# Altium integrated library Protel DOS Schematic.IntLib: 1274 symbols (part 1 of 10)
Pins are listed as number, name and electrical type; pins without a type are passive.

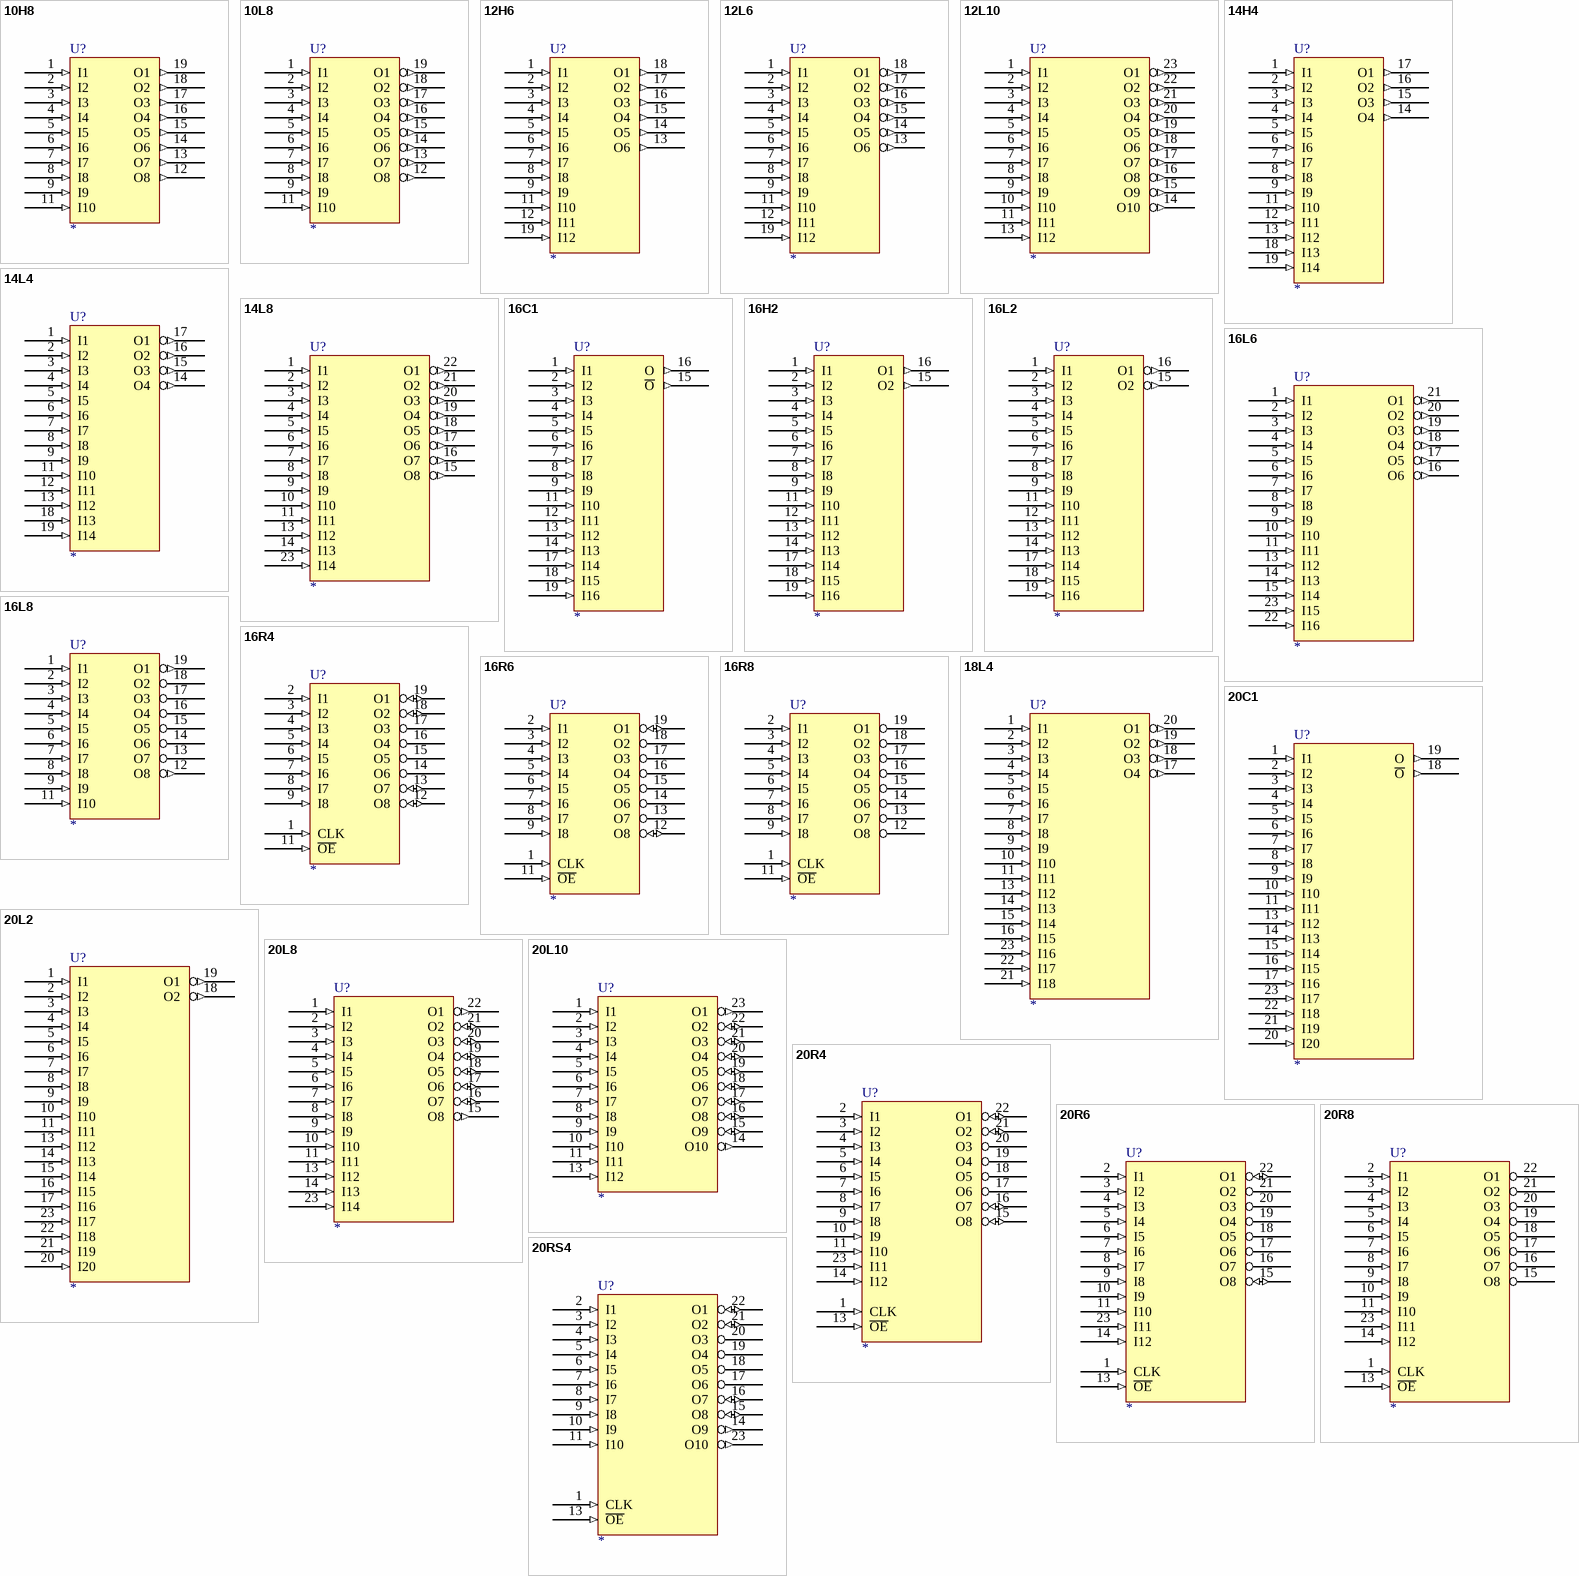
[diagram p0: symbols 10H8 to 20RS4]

## 10H8
designator U?
footprint DIP-20
pins: 1 I1 (in), 2 I2 (in), 3 I3 (in), 4 I4 (in), 5 I5 (in), 6 I6 (in), 7 I7 (in), 8 I8 (in), 9 I9 (in), 10 GND (power) hidden to GND, 11 I10 (in), 12 O8 (out), 13 O7 (out), 14 O6 (out), 15 O5 (out), 16 O4 (out), 17 O3 (out), 18 O2 (out), 19 O1 (out), 20 VCC (power) hidden to VCC
2 alternate drawings of the same symbol

## 10L8
designator U?
footprint DIP-20
pins: 1 I1 (in), 2 I2 (in), 3 I3 (in), 4 I4 (in), 5 I5 (in), 6 I6 (in), 7 I7 (in), 8 I8 (in), 9 I9 (in), 10 GND (power) hidden to GND, 11 I10 (in), 12 O8 (out), 13 O7 (out), 14 O6 (out), 15 O5 (out), 16 O4 (out), 17 O3 (out), 18 O2 (out), 19 O1 (out), 20 VCC (power) hidden to VCC
2 alternate drawings of the same symbol

## 12H6
designator U?
footprint DIP-20
pins: 1 I1 (in), 2 I2 (in), 3 I3 (in), 4 I4 (in), 5 I5 (in), 6 I6 (in), 7 I7 (in), 8 I8 (in), 9 I9 (in), 10 GND (power) hidden to GND, 11 I10 (in), 12 I11 (in), 13 O6 (out), 14 O5 (out), 15 O4 (out), 16 O3 (out), 17 O2 (out), 18 O1 (out), 19 I12 (in), 20 VCC (power) hidden to VCC
2 alternate drawings of the same symbol

## 12L6
designator U?
footprint DIP-20
pins: 1 I1 (in), 2 I2 (in), 3 I3 (in), 4 I4 (in), 5 I5 (in), 6 I6 (in), 7 I7 (in), 8 I8 (in), 9 I9 (in), 10 GND (power) hidden to GND, 11 I10 (in), 12 I11 (in), 13 O6 (out), 14 O5 (out), 15 O4 (out), 16 O3 (out), 17 O2 (out), 18 O1 (out), 19 I12 (in), 20 VCC (power) hidden to VCC
2 alternate drawings of the same symbol

## 12L10
designator U?
footprint DIP-24
pins: 1 I1 (in), 2 I2 (in), 3 I3 (in), 4 I4 (in), 5 I5 (in), 6 I6 (in), 7 I7 (in), 8 I8 (in), 9 I9 (in), 10 I10 (in), 11 I11 (in), 12 GND (power) hidden to GND, 13 I12 (in), 14 O10 (out), 15 O9 (out), 16 O8 (out), 17 O7 (out), 18 O6 (out), 19 O5 (out), 20 O4 (out), 21 O3 (out), 22 O2 (out), 23 O1 (out), 24 VCC (power) hidden to VCC
2 alternate drawings of the same symbol

## 14H4
designator U?
footprint DIP-20
pins: 1 I1 (in), 2 I2 (in), 3 I3 (in), 4 I4 (in), 5 I5 (in), 6 I6 (in), 7 I7 (in), 8 I8 (in), 9 I9 (in), 10 GND (power) hidden to GND, 11 I10 (in), 12 I11 (in), 13 I12 (in), 14 O4 (out), 15 O3 (out), 16 O2 (out), 17 O1 (out), 18 I13 (in), 19 I14 (in), 20 VCC (power) hidden to VCC
2 alternate drawings of the same symbol

## 14L4
designator U?
footprint DIP-20
pins: 1 I1 (in), 2 I2 (in), 3 I3 (in), 4 I4 (in), 5 I5 (in), 6 I6 (in), 7 I7 (in), 8 I8 (in), 9 I9 (in), 10 GND (power) hidden to GND, 11 I10 (in), 12 I11 (in), 13 I12 (in), 14 O4 (out), 15 O3 (out), 16 O2 (out), 17 O1 (out), 18 I13 (in), 19 I14 (in), 20 VCC (power) hidden to VCC
2 alternate drawings of the same symbol

## 14L8
designator U?
footprint DIP-24
pins: 1 I1 (in), 2 I2 (in), 3 I3 (in), 4 I4 (in), 5 I5 (in), 6 I6 (in), 7 I7 (in), 8 I8 (in), 9 I9 (in), 10 I10 (in), 11 I11 (in), 12 GND (power) hidden to GND, 13 I12 (in), 14 I13 (in), 15 O8 (out), 16 O7 (out), 17 O6 (out), 18 O5 (out), 19 O4 (out), 20 O3 (out), 21 O2 (out), 22 O1 (out), 23 I14 (in), 24 VCC (power) hidden to VCC
2 alternate drawings of the same symbol

## 16C1
designator U?
footprint DIP-20
pins: 1 I1 (in), 2 I2 (in), 3 I3 (in), 4 I4 (in), 5 I5 (in), 6 I6 (in), 7 I7 (in), 8 I8 (in), 9 I9 (in), 10 GND (power) hidden to GND, 11 I10 (in), 12 I11 (in), 13 I12 (in), 14 I13 (in), 15 ~{O} (out), 16 O (out), 17 I14 (in), 18 I15 (in), 19 I16 (in), 20 VCC (power) hidden to VCC
2 alternate drawings of the same symbol

## 16H2
designator U?
footprint DIP-20
pins: 1 I1 (in), 2 I2 (in), 3 I3 (in), 4 I4 (in), 5 I5 (in), 6 I6 (in), 7 I7 (in), 8 I8 (in), 9 I9 (in), 10 GND (power) hidden to GND, 11 I10 (in), 12 I11 (in), 13 I12 (in), 14 I13 (in), 15 O2 (out), 16 O1 (out), 17 I14 (in), 18 I15 (in), 19 I16 (in), 20 VCC (power) hidden to VCC
2 alternate drawings of the same symbol

## 16L2
designator U?
footprint DIP-20
pins: 1 I1 (in), 2 I2 (in), 3 I3 (in), 4 I4 (in), 5 I5 (in), 6 I6 (in), 7 I7 (in), 8 I8 (in), 9 I9 (in), 10 GND (power) hidden to GND, 11 I10 (in), 12 I11 (in), 13 I12 (in), 14 I13 (in), 15 O2 (out), 16 O1 (out), 17 I14 (in), 18 I15 (in), 19 I16 (in), 20 VCC (power) hidden to VCC
2 alternate drawings of the same symbol

## 16L6
designator U?
footprint DIP-24
pins: 1 I1 (in), 2 I2 (in), 3 I3 (in), 4 I4 (in), 5 I5 (in), 6 I6 (in), 7 I7 (in), 8 I8 (in), 9 I9 (in), 10 I10 (in), 11 I11 (in), 12 GND (power) hidden to GND, 13 I12 (in), 14 I13 (in), 15 I14 (in), 16 O6 (out), 17 O5 (out), 18 O4 (out), 19 O3 (out), 20 O2 (out), 21 O1 (out), 22 I16 (in), 23 I15 (in), 24 VCC (power) hidden to VCC
2 alternate drawings of the same symbol

## 16L8
designator U?
footprint DIP-20
pins: 1 I1 (in), 2 I2 (in), 3 I3 (in), 4 I4 (in), 5 I5 (in), 6 I6 (in), 7 I7 (in), 8 I8 (in), 9 I9 (in), 10 GND (power) hidden to GND, 11 I10 (in), 12 O8 (out), 13 O7 (hiz), 14 O6 (hiz), 15 O5 (hiz), 16 O4 (hiz), 17 O3 (hiz), 18 O2 (hiz), 19 O1 (out), 20 VCC (power) hidden to VCC
2 alternate drawings of the same symbol

## 16R4
designator U?
footprint DIP-20
pins: 1 CLK (in), 2 I1 (in), 3 I2 (in), 4 I3 (in), 5 I4 (in), 6 I5 (in), 7 I6 (in), 8 I7 (in), 9 I8 (in), 10 GND (power) hidden to GND, 11 ~{OE} (in), 12 O8 (io), 13 O7 (io), 14 O6 (hiz), 15 O5 (hiz), 16 O4 (hiz), 17 O3 (hiz), 18 O2 (io), 19 O1 (io), 20 VCC (power) hidden to VCC
2 alternate drawings of the same symbol

## 16R6
designator U?
footprint DIP-20
pins: 1 CLK (in), 2 I1 (in), 3 I2 (in), 4 I3 (in), 5 I4 (in), 6 I5 (in), 7 I6 (in), 8 I7 (in), 9 I8 (in), 10 GND (power) hidden to GND, 11 ~{OE} (in), 12 O8 (io), 13 O7 (hiz), 14 O6 (hiz), 15 O5 (hiz), 16 O4 (hiz), 17 O3 (hiz), 18 O2 (hiz), 19 O1 (io), 20 VCC (power) hidden to VCC
2 alternate drawings of the same symbol

## 16R8
designator U?
footprint DIP-20
pins: 1 CLK (in), 2 I1 (in), 3 I2 (in), 4 I3 (in), 5 I4 (in), 6 I5 (in), 7 I6 (in), 8 I7 (in), 9 I8 (in), 10 GND (power) hidden to GND, 11 ~{OE} (in), 12 O8 (hiz), 13 O7 (hiz), 14 O6 (hiz), 15 O5 (hiz), 16 O4 (hiz), 17 O3 (hiz), 18 O2 (hiz), 19 O1 (hiz), 20 VCC (power) hidden to VCC
2 alternate drawings of the same symbol

## 18L4
designator U?
footprint DIP-24
pins: 1 I1 (in), 2 I2 (in), 3 I3 (in), 4 I4 (in), 5 I5 (in), 6 I6 (in), 7 I7 (in), 8 I8 (in), 9 I9 (in), 10 I10 (in), 11 I11 (in), 12 GND (power) hidden to GND, 13 I12 (in), 14 I13 (in), 15 I14 (in), 16 I15 (in), 17 O4 (out), 18 O3 (out), 19 O2 (out), 20 O1 (out), 21 I18 (in), 22 I17 (in), 23 I16 (in), 24 VCC (power) hidden to VCC
2 alternate drawings of the same symbol

## 20C1
designator U?
footprint DIP-24
pins: 1 I1 (in), 2 I2 (in), 3 I3 (in), 4 I4 (in), 5 I5 (in), 6 I6 (in), 7 I7 (in), 8 I8 (in), 9 I9 (in), 10 I10 (in), 11 I11 (in), 12 GND (power) hidden to GND, 13 I12 (in), 14 I13 (in), 15 I14 (in), 16 I15 (in), 17 I16 (in), 18 ~{O} (out), 19 O (out), 20 I20 (in), 21 I19 (in), 22 I18 (in), 23 I17 (in), 24 VCC (power) hidden to VCC
2 alternate drawings of the same symbol

## 20L2
designator U?
footprint DIP-24
pins: 1 I1 (in), 2 I2 (in), 3 I3 (in), 4 I4 (in), 5 I5 (in), 6 I6 (in), 7 I7 (in), 8 I8 (in), 9 I9 (in), 10 I10 (in), 11 I11 (in), 12 GND (power) hidden to GND, 13 I12 (in), 14 I13 (in), 15 I14 (in), 16 I15 (in), 17 I16 (in), 18 O2 (out), 19 O1 (out), 20 I20 (in), 21 I19 (in), 22 I18 (in), 23 I17 (in), 24 VCC (power) hidden to VCC
2 alternate drawings of the same symbol

## 20L8
designator U?
footprint DIP-24
pins: 1 I1 (in), 2 I2 (in), 3 I3 (in), 4 I4 (in), 5 I5 (in), 6 I6 (in), 7 I7 (in), 8 I8 (in), 9 I9 (in), 10 I10 (in), 11 I11 (in), 12 GND (power) hidden to GND, 13 I12 (in), 14 I13 (in), 15 O8 (out), 16 O7 (io), 17 O6 (io), 18 O5 (io), 19 O4 (io), 20 O3 (io), 21 O2 (io), 22 O1 (out), 23 I14 (in), 24 VCC (power) hidden to VCC
2 alternate drawings of the same symbol

## 20L10
designator U?
footprint DIP-24
pins: 1 I1 (in), 2 I2 (in), 3 I3 (in), 4 I4 (in), 5 I5 (in), 6 I6 (in), 7 I7 (in), 8 I8 (in), 9 I9 (in), 10 I10 (in), 11 I11 (in), 12 GND (power) hidden to GND, 13 I12 (in), 14 O10 (out), 15 O9 (io), 16 O8 (io), 17 O7 (io), 18 O6 (io), 19 O5 (io), 20 O4 (io), 21 O3 (io), 22 O2 (io), 23 O1 (out), 24 VCC (power) hidden to VCC
2 alternate drawings of the same symbol

## 20R4
designator U?
footprint DIP-24
pins: 1 CLK (in), 2 I1 (in), 3 I2 (in), 4 I3 (in), 5 I4 (in), 6 I5 (in), 7 I6 (in), 8 I7 (in), 9 I8 (in), 10 I9 (in), 11 I10 (in), 12 GND (power) hidden to GND, 13 ~{OE} (in), 14 I12 (in), 15 O8 (io), 16 O7 (io), 17 O6 (hiz), 18 O5 (hiz), 19 O4 (hiz), 20 O3 (hiz), 21 O2 (io), 22 O1 (io), 23 I11 (in), 24 VCC (power) hidden to VCC
2 alternate drawings of the same symbol

## 20R6
designator U?
footprint DIP-24
pins: 1 CLK (in), 2 I1 (in), 3 I2 (in), 4 I3 (in), 5 I4 (in), 6 I5 (in), 7 I6 (in), 8 I7 (in), 9 I8 (in), 10 I9 (in), 11 I10 (in), 12 GND (power) hidden to GND, 13 ~{OE} (in), 14 I12 (in), 15 O8 (io), 16 O7 (hiz), 17 O6 (hiz), 18 O5 (hiz), 19 O4 (hiz), 20 O3 (hiz), 21 O2 (hiz), 22 O1 (io), 23 I11 (in), 24 VCC (power) hidden to VCC
2 alternate drawings of the same symbol

## 20R8
designator U?
footprint DIP-24
pins: 1 CLK (in), 2 I1 (in), 3 I2 (in), 4 I3 (in), 5 I4 (in), 6 I5 (in), 7 I6 (in), 8 I7 (in), 9 I8 (in), 10 I9 (in), 11 I10 (in), 12 GND (power) hidden to GND, 13 ~{OE} (in), 14 I12 (in), 15 O8 (hiz), 16 O7 (hiz), 17 O6 (hiz), 18 O5 (hiz), 19 O4 (hiz), 20 O3 (hiz), 21 O2 (hiz), 22 O1 (hiz), 23 I11 (in), 24 VCC (power) hidden to VCC
2 alternate drawings of the same symbol

## 20RS4
designator U?
footprint DIP-24
pins: 1 CLK (in), 2 I1 (in), 3 I2 (in), 4 I3 (in), 5 I4 (in), 6 I5 (in), 7 I6 (in), 8 I7 (in), 9 I8 (in), 10 I9 (in), 11 I10 (in), 12 GND (power) hidden to GND, 13 ~{OE} (in), 14 O9 (out), 15 O8 (io), 16 O7 (io), 17 O6 (hiz), 18 O5 (hiz), 19 O4 (hiz), 20 O3 (hiz), 21 O2 (io), 22 O1 (io), 23 O10 (out), 24 VCC (power) hidden to VCC
2 alternate drawings of the same symbol

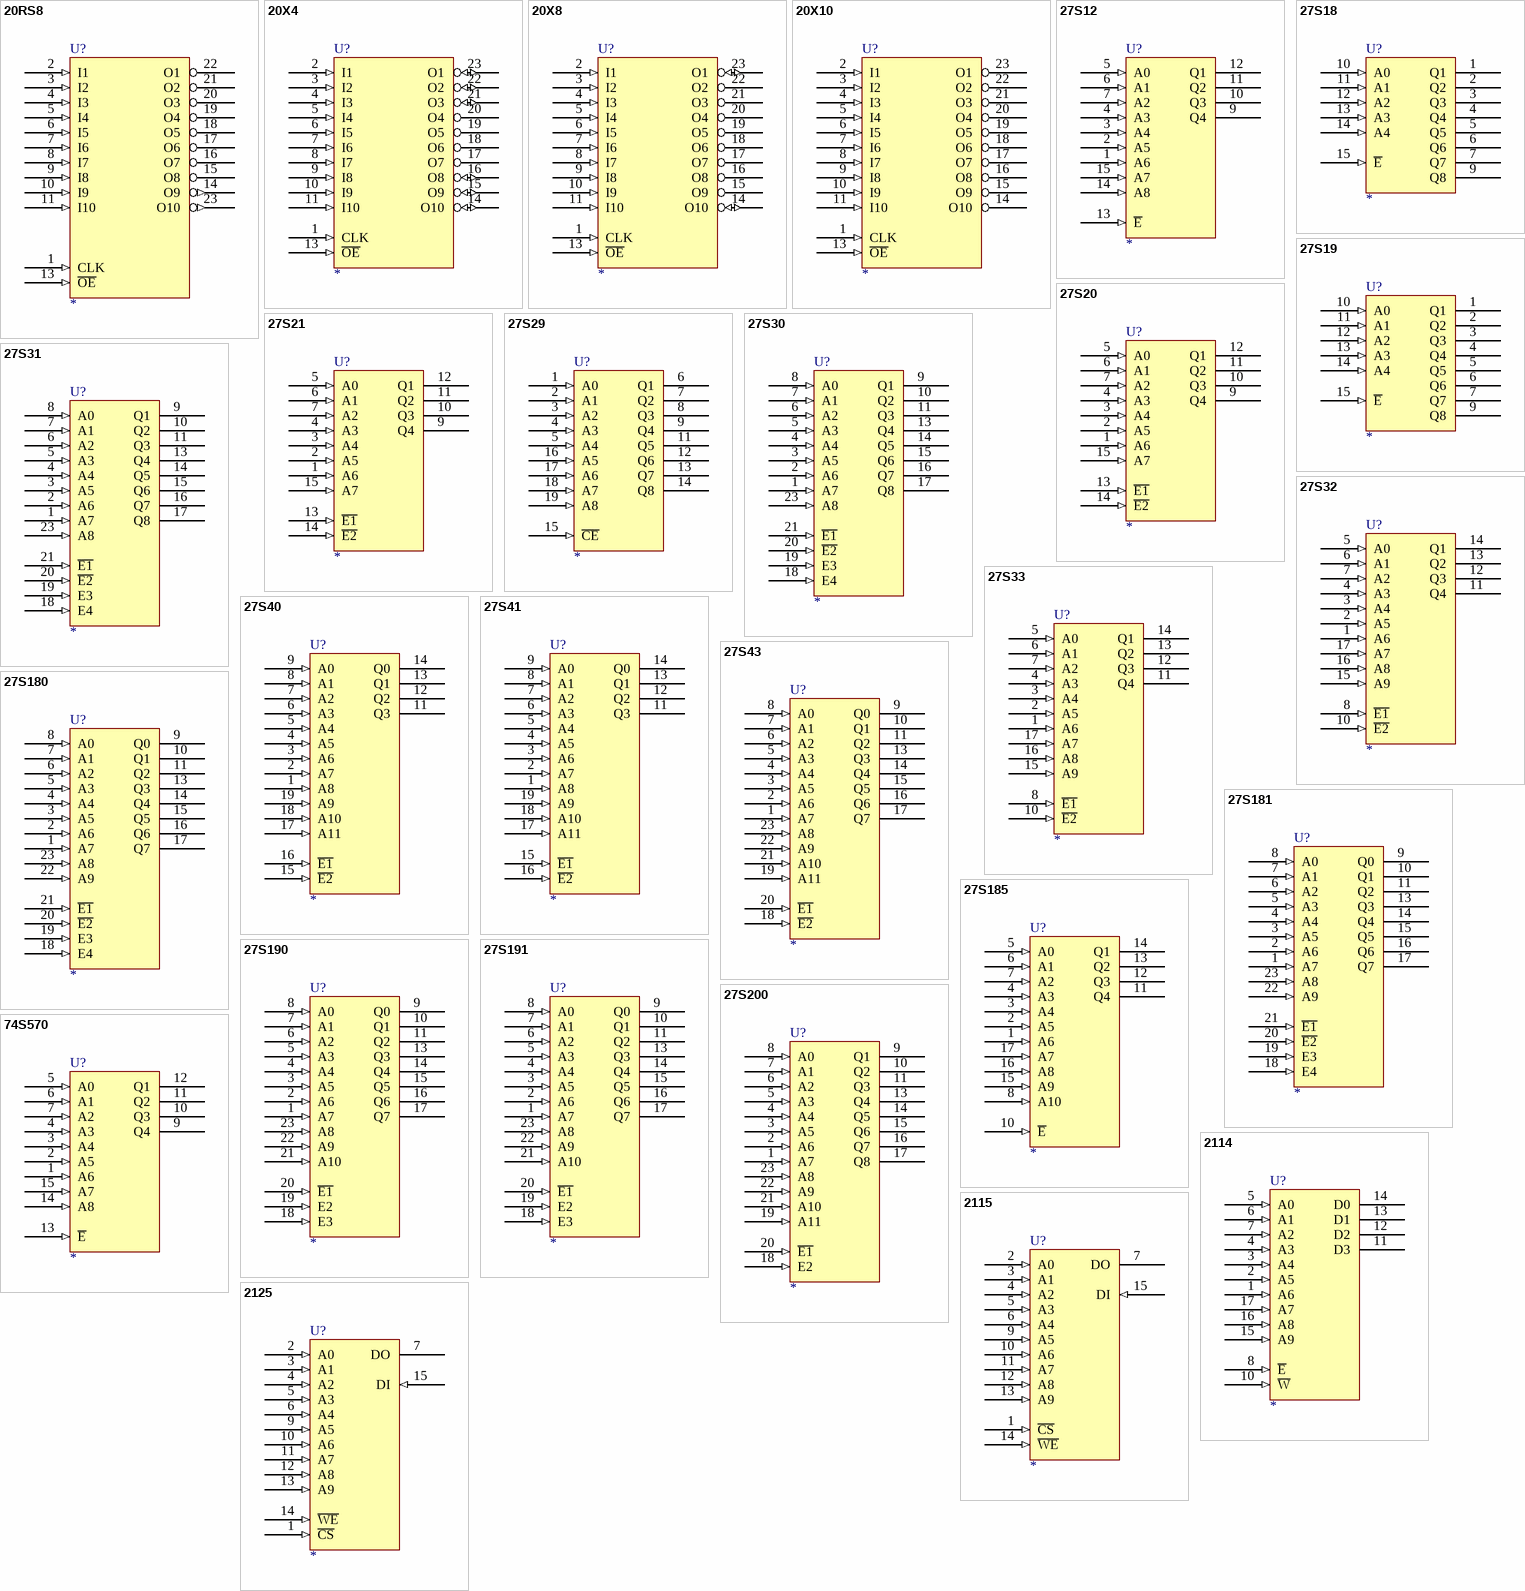
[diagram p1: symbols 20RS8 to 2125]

## 20RS8
designator U?
footprint DIP-24
pins: 1 CLK (in), 2 I1 (in), 3 I2 (in), 4 I3 (in), 5 I4 (in), 6 I5 (in), 7 I6 (in), 8 I7 (in), 9 I8 (in), 10 I9 (in), 11 I10 (in), 12 GND (power) hidden to GND, 13 ~{OE} (in), 14 O9 (out), 15 O8 (hiz), 16 O7 (hiz), 17 O6 (hiz), 18 O5 (hiz), 19 O4 (hiz), 20 O3 (hiz), 21 O2 (hiz), 22 O1 (hiz), 23 O10 (out), 24 VCC (power) hidden to VCC
2 alternate drawings of the same symbol

## 20X4
designator U?
footprint DIP-24
pins: 1 CLK (in), 2 I1 (in), 3 I2 (in), 4 I3 (in), 5 I4 (in), 6 I5 (in), 7 I6 (in), 8 I7 (in), 9 I8 (in), 10 I9 (in), 11 I10 (in), 12 GND (power) hidden to GND, 13 ~{OE} (in), 14 O10 (io), 15 O9 (io), 16 O8 (io), 17 O7 (hiz), 18 O6 (hiz), 19 O5 (hiz), 20 O4 (hiz), 21 O3 (io), 22 O2 (io), 23 O1 (io), 24 VCC (power) hidden to VCC
2 alternate drawings of the same symbol

## 20X8
designator U?
footprint DIP-24
pins: 1 CLK (in), 2 I1 (in), 3 I2 (in), 4 I3 (in), 5 I4 (in), 6 I5 (in), 7 I6 (in), 8 I7 (in), 9 I8 (in), 10 I9 (in), 11 I10 (in), 12 GND (power) hidden to GND, 13 ~{OE} (in), 14 O10 (io), 15 O9 (hiz), 16 O8 (hiz), 17 O7 (hiz), 18 O6 (hiz), 19 O5 (hiz), 20 O4 (hiz), 21 O3 (hiz), 22 O2 (hiz), 23 O1 (io), 24 VCC (power) hidden to VCC
2 alternate drawings of the same symbol

## 20X10
designator U?
footprint DIP-24
pins: 1 CLK (in), 2 I1 (in), 3 I2 (in), 4 I3 (in), 5 I4 (in), 6 I5 (in), 7 I6 (in), 8 I7 (in), 9 I8 (in), 10 I9 (in), 11 I10 (in), 12 GND (power) hidden to GND, 13 ~{OE} (in), 14 O10 (hiz), 15 O9 (hiz), 16 O8 (hiz), 17 O7 (hiz), 18 O6 (hiz), 19 O5 (hiz), 20 O4 (hiz), 21 O3 (hiz), 22 O2 (hiz), 23 O1 (hiz), 24 VCC (power) hidden to VCC
2 alternate drawings of the same symbol

## 27S12
designator U?
footprint DIP-16
pins: 1 A6 (in), 2 A5 (in), 3 A4 (in), 4 A3 (in), 5 A0 (in), 6 A1 (in), 7 A2 (in), 8 GND (power) hidden to GND, 9 Q4 (hiz), 10 Q3 (hiz), 11 Q2 (hiz), 12 Q1 (hiz), 13 ~{E} (in), 14 A8 (in), 15 A7 (in), 16 VCC (power) hidden to VCC
2 alternate drawings of the same symbol

## 27S18
designator U?
footprint DIP-16
pins: 1 Q1 (oc), 2 Q2 (oc), 3 Q3 (oc), 4 Q4 (oc), 5 Q5 (oc), 6 Q6 (oc), 7 Q7 (oc), 8 GND (power) hidden to GND, 9 Q8 (oc), 10 A0 (in), 11 A1 (in), 12 A2 (in), 13 A3 (in), 14 A4 (in), 15 ~{E} (in), 16 VCC (power) hidden to VCC
2 alternate drawings of the same symbol

## 27S19
designator U?
footprint DIP-16
pins: 1 Q1 (hiz), 2 Q2 (hiz), 3 Q3 (hiz), 4 Q4 (hiz), 5 Q5 (hiz), 6 Q6 (hiz), 7 Q7 (hiz), 8 GND (power) hidden to GND, 9 Q8 (hiz), 10 A0 (in), 11 A1 (in), 12 A2 (in), 13 A3 (in), 14 A4 (in), 15 ~{E} (in), 16 VCC (power) hidden to VCC
2 alternate drawings of the same symbol

## 27S20
designator U?
footprint DIP-16
pins: 1 A6 (in), 2 A5 (in), 3 A4 (in), 4 A3 (in), 5 A0 (in), 6 A1 (in), 7 A2 (in), 8 GND (power) hidden to GND, 9 Q4 (oc), 10 Q3 (oc), 11 Q2 (oc), 12 Q1 (oc), 13 ~{E1} (in), 14 ~{E2} (in), 15 A7 (in), 16 VCC (power) hidden to VCC
2 alternate drawings of the same symbol

## 27S21
designator U?
footprint DIP-16
pins: 1 A6 (in), 2 A5 (in), 3 A4 (in), 4 A3 (in), 5 A0 (in), 6 A1 (in), 7 A2 (in), 8 GND (power) hidden to GND, 9 Q4 (hiz), 10 Q3 (hiz), 11 Q2 (hiz), 12 Q1 (hiz), 13 ~{E1} (in), 14 ~{E2} (in), 15 A7 (in), 16 VCC (power) hidden to VCC
2 alternate drawings of the same symbol

## 27S29
designator U?
footprint DIP-20
pins: 1 A0 (in), 2 A1 (in), 3 A2 (in), 4 A3 (in), 5 A4 (in), 6 Q1 (hiz), 7 Q2 (hiz), 8 Q3 (hiz), 9 Q4 (hiz), 10 GND (power) hidden to GND, 11 Q5 (hiz), 12 Q6 (hiz), 13 Q7 (hiz), 14 Q8 (hiz), 15 ~{CE} (in), 16 A5 (in), 17 A6 (in), 18 A7 (in), 19 A8 (in), 20 VCC (power) hidden to VCC
2 alternate drawings of the same symbol

## 27S30
designator U?
footprint DIP-24
pins: 1 A7 (in), 2 A6 (in), 3 A5 (in), 4 A4 (in), 5 A3 (in), 6 A2 (in), 7 A1 (in), 8 A0 (in), 9 Q1 (oc), 10 Q2 (oc), 11 Q3 (oc), 12 GND (power) hidden to GND, 13 Q4 (oc), 14 Q5 (oc), 15 Q6 (oc), 16 Q7 (oc), 17 Q8 (oc), 18 E4 (in), 19 E3 (in), 20 ~{E2} (in), 21 ~{E1} (in), 23 A8 (in), 24 VCC (power) hidden to VCC
2 alternate drawings of the same symbol

## 27S31
designator U?
footprint DIP-24
pins: 1 A7 (in), 2 A6 (in), 3 A5 (in), 4 A4 (in), 5 A3 (in), 6 A2 (in), 7 A1 (in), 8 A0 (in), 9 Q1 (hiz), 10 Q2 (hiz), 11 Q3 (hiz), 12 GND (power) hidden to GND, 13 Q4 (hiz), 14 Q5 (hiz), 15 Q6 (hiz), 16 Q7 (hiz), 17 Q8 (hiz), 18 E4 (in), 19 E3 (in), 20 ~{E2} (in), 21 ~{E1} (in), 23 A8 (in), 24 VCC (power) hidden to VCC
2 alternate drawings of the same symbol

## 27S32
designator U?
footprint DIP-18
pins: 1 A6 (in), 2 A5 (in), 3 A4 (in), 4 A3 (in), 5 A0 (in), 6 A1 (in), 7 A2 (in), 8 ~{E1} (in), 9 GND (power) hidden to GND, 10 ~{E2} (in), 11 Q4 (oc), 12 Q3 (oc), 13 Q2 (oc), 14 Q1 (oc), 15 A9 (in), 16 A8 (in), 17 A7 (in), 18 VCC (power) hidden to VCC
2 alternate drawings of the same symbol

## 27S33
designator U?
footprint DIP-18
pins: 1 A6 (in), 2 A5 (in), 3 A4 (in), 4 A3 (in), 5 A0 (in), 6 A1 (in), 7 A2 (in), 8 ~{E1} (in), 9 GND (power) hidden to GND, 10 ~{E2} (in), 11 Q4 (hiz), 12 Q3 (hiz), 13 Q2 (hiz), 14 Q1 (hiz), 15 A9 (in), 16 A8 (in), 17 A7 (in), 18 VCC (power) hidden to VCC
2 alternate drawings of the same symbol

## 27S40
designator U?
footprint DIP-20
pins: 1 A8 (in), 2 A7 (in), 3 A6 (in), 4 A5 (in), 5 A4 (in), 6 A3 (in), 7 A2 (in), 8 A1 (in), 9 A0 (in), 10 GND (power) hidden to GND, 11 Q3 (oc), 12 Q2 (oc), 13 Q1 (oc), 14 Q0 (oc), 15 ~{E2} (in), 16 ~{E1} (in), 17 A11 (in), 18 A10 (in), 19 A9 (in), 20 VCC (power) hidden to VCC
2 alternate drawings of the same symbol

## 27S41
designator U?
footprint DIP-20
pins: 1 A8 (in), 2 A7 (in), 3 A6 (in), 4 A5 (in), 5 A4 (in), 6 A3 (in), 7 A2 (in), 8 A1 (in), 9 A0 (in), 10 GND (power) hidden to GND, 11 Q3 (hiz), 12 Q2 (hiz), 13 Q1 (hiz), 14 Q0 (hiz), 15 ~{E1} (in), 16 ~{E2} (in), 17 A11 (in), 18 A10 (in), 19 A9 (in), 20 VCC (power) hidden to VCC
2 alternate drawings of the same symbol

## 27S43
designator U?
footprint DIP-24
pins: 1 A7 (in), 2 A6 (in), 3 A5 (in), 4 A4 (in), 5 A3 (in), 6 A2 (in), 7 A1 (in), 8 A0 (in), 9 Q0 (hiz), 10 Q1 (hiz), 11 Q2 (hiz), 12 GND (power) hidden to GND, 13 Q3 (hiz), 14 Q4 (hiz), 15 Q5 (hiz), 16 Q6 (hiz), 17 Q7 (hiz), 18 ~{E2} (in), 19 A11 (in), 20 ~{E1} (in), 21 A10 (in), 22 A9 (in), 23 A8 (in), 24 VCC (power) hidden to VCC
2 alternate drawings of the same symbol

## 27S180
designator U?
footprint DIP-24
pins: 1 A7 (in), 2 A6 (in), 3 A5 (in), 4 A4 (in), 5 A3 (in), 6 A2 (in), 7 A1 (in), 8 A0 (in), 9 Q0 (oc), 10 Q1 (oc), 11 Q2 (oc), 12 GND (power) hidden to GND, 13 Q3 (oc), 14 Q4 (oc), 15 Q5 (oc), 16 Q6 (oc), 17 Q7 (oc), 18 E4 (in), 19 E3 (in), 20 ~{E2} (in), 21 ~{E1} (in), 22 A9 (in), 23 A8 (in), 24 VCC (power) hidden to VCC
2 alternate drawings of the same symbol

## 27S181
designator U?
footprint DIP-24
pins: 1 A7 (in), 2 A6 (in), 3 A5 (in), 4 A4 (in), 5 A3 (in), 6 A2 (in), 7 A1 (in), 8 A0 (in), 9 Q0 (hiz), 10 Q1 (hiz), 11 Q2 (hiz), 12 GND (power) hidden to GND, 13 Q3 (hiz), 14 Q4 (hiz), 15 Q5 (hiz), 16 Q6 (hiz), 17 Q7 (hiz), 18 E4 (in), 19 E3 (in), 20 ~{E2} (in), 21 ~{E1} (in), 22 A9 (in), 23 A8 (in), 24 VCC (power) hidden to VCC
2 alternate drawings of the same symbol

## 27S185
designator U?
footprint DIP-18
pins: 1 A6 (in), 2 A5 (in), 3 A4 (in), 4 A3 (in), 5 A0 (in), 6 A1 (in), 7 A2 (in), 8 A10 (in), 9 GND (power) hidden to GND, 10 ~{E} (in), 11 Q4 (hiz), 12 Q3 (hiz), 13 Q2 (hiz), 14 Q1 (hiz), 15 A9 (in), 16 A8 (in), 17 A7 (in), 18 VCC (power) hidden to VCC
2 alternate drawings of the same symbol

## 27S190
designator U?
footprint DIP-24
pins: 1 A7 (in), 2 A6 (in), 3 A5 (in), 4 A4 (in), 5 A3 (in), 6 A2 (in), 7 A1 (in), 8 A0 (in), 9 Q0 (oc), 10 Q1 (oc), 11 Q2 (oc), 12 GND (power) hidden to GND, 13 Q3 (oc), 14 Q4 (oc), 15 Q5 (oc), 16 Q6 (oc), 17 Q7 (oc), 18 E3 (in), 19 E2 (in), 20 ~{E1} (in), 21 A10 (in), 22 A9 (in), 23 A8 (in), 24 VCC (power) hidden to VCC
2 alternate drawings of the same symbol

## 27S191
designator U?
footprint DIP-24
pins: 1 A7 (in), 2 A6 (in), 3 A5 (in), 4 A4 (in), 5 A3 (in), 6 A2 (in), 7 A1 (in), 8 A0 (in), 9 Q0 (hiz), 10 Q1 (hiz), 11 Q2 (hiz), 12 GND (power) hidden to GND, 13 Q3 (hiz), 14 Q4 (hiz), 15 Q5 (hiz), 16 Q6 (hiz), 17 Q7 (hiz), 18 E3 (in), 19 E2 (in), 20 ~{E1} (in), 21 A10 (in), 22 A9 (in), 23 A8 (in), 24 VCC (power) hidden to VCC
2 alternate drawings of the same symbol

## 27S200
designator U?
footprint DIP-24
pins: 1 A7 (in), 2 A6 (in), 3 A5 (in), 4 A4 (in), 5 A3 (in), 6 A2 (in), 7 A1 (in), 8 A0 (in), 9 Q1 (hiz), 10 Q2 (hiz), 11 Q3 (hiz), 12 GND (power) hidden to GND, 13 Q4 (hiz), 14 Q5 (hiz), 15 Q6 (hiz), 16 Q7 (hiz), 17 Q8 (hiz), 18 E2 (in), 19 A11 (in), 20 ~{E1} (in), 21 A10 (in), 22 A9 (in), 23 A8 (in), 24 VCC (power) hidden to VCC
2 alternate drawings of the same symbol

## 74S570
designator U?
footprint DIP-16
pins: 1 A6 (in), 2 A5 (in), 3 A4 (in), 4 A3 (in), 5 A0 (in), 6 A1 (in), 7 A2 (in), 8 GND (power) hidden to GND, 9 Q4 (oc), 10 Q3 (oc), 11 Q2 (oc), 12 Q1 (oc), 13 ~{E} (in), 14 A8 (in), 15 A7 (in), 16 VCC (power) hidden to VCC
2 alternate drawings of the same symbol

## 2114
designator U?
footprint DIP-18
pins: 1 A6 (in), 2 A5 (in), 3 A4 (in), 4 A3 (in), 5 A0 (in), 6 A1 (in), 7 A2 (in), 8 ~{E} (in), 9 GND (power) hidden to GND, 10 ~{W} (in), 11 D3 (hiz), 12 D2 (hiz), 13 D1 (hiz), 14 D0 (hiz), 15 A9 (in), 16 A8 (in), 17 A7 (in), 18 VCC (power) hidden to VCC
2 alternate drawings of the same symbol

## 2115
designator U?
footprint DIP-16
pins: 1 ~{CS} (in), 2 A0 (in), 3 A1 (in), 4 A2 (in), 5 A3 (in), 6 A4 (in), 7 DO (oc), 8 GND (power) hidden to GND, 9 A5 (in), 10 A6 (in), 11 A7 (in), 12 A8 (in), 13 A9 (in), 14 ~{WE} (in), 15 DI (in), 16 VCC (power) hidden to VCC
2 alternate drawings of the same symbol

## 2125
designator U?
footprint DIP-16
pins: 1 ~{CS} (in), 2 A0 (in), 3 A1 (in), 4 A2 (in), 5 A3 (in), 6 A4 (in), 7 DO (hiz), 8 GND (power) hidden to GND, 9 A5 (in), 10 A6 (in), 11 A7 (in), 12 A8 (in), 13 A9 (in), 14 ~{WE} (in), 15 DI (in), 16 VCC (power) hidden to VCC
2 alternate drawings of the same symbol

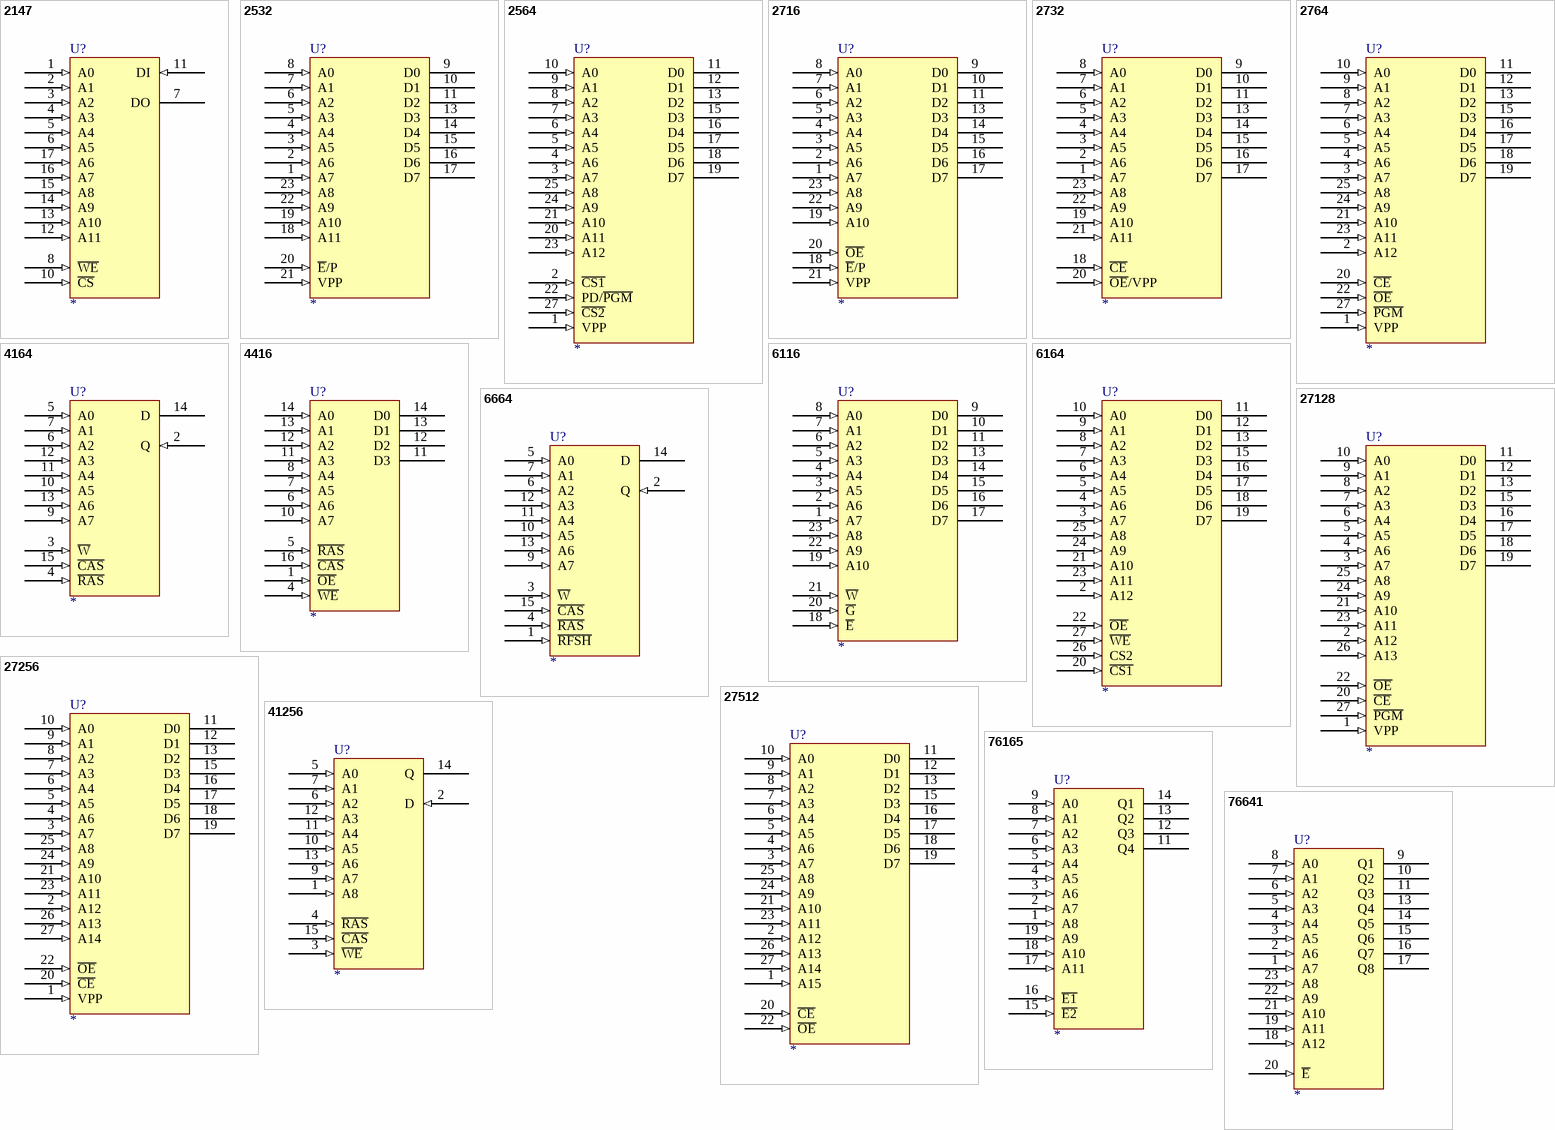
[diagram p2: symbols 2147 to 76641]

## 2147
designator U?
footprint DIP-18
pins: 1 A0 (in), 2 A1 (in), 3 A2 (in), 4 A3 (in), 5 A4 (in), 6 A5 (in), 7 DO (hiz), 8 ~{WE} (in), 9 GND (power) hidden to GND, 10 ~{CS} (in), 11 DI (in), 12 A11 (in), 13 A10 (in), 14 A9 (in), 15 A8 (in), 16 A7 (in), 17 A6 (in), 18 VCC (power) hidden to VCC
2 alternate drawings of the same symbol

## 2532
designator U?
footprint DIP-24
pins: 1 A7 (in), 2 A6 (in), 3 A5 (in), 4 A4 (in), 5 A3 (in), 6 A2 (in), 7 A1 (in), 8 A0 (in), 9 D0 (hiz), 10 D1 (hiz), 11 D2 (hiz), 12 GND (power) hidden to GND, 13 D3 (hiz), 14 D4 (hiz), 15 D5 (hiz), 16 D6 (hiz), 17 D7 (hiz), 18 A11 (in), 19 A10 (in), 20 ~{E}/P (in), 21 VPP (in), 22 A9 (in), 23 A8 (in), 24 VCC (power) hidden to VCC
2 alternate drawings of the same symbol

## 2564
designator U?
footprint DIP-24
pins: 1 VPP (in), 2 ~{CS1} (in), 3 A7 (in), 4 A6 (in), 5 A5 (in), 6 A4 (in), 7 A3 (in), 8 A2 (in), 9 A1 (in), 10 A0 (in), 11 D0 (hiz), 12 D1 (hiz), 13 D2 (hiz), 14 GND (power) hidden to GND, 15 D3 (hiz), 16 D4 (hiz), 17 D5 (hiz), 18 D6 (hiz), 19 D7 (hiz), 20 A11 (in), 21 A10 (in), 22 PD/~{PGM} (in), 23 A12 (in), 24 A9 (in), 25 A8 (in), 27 ~{CS2} (in), 28 VCC (power) hidden to VCC
2 alternate drawings of the same symbol

## 2716
designator U?
footprint DIP-24
pins: 1 A7 (in), 2 A6 (in), 3 A5 (in), 4 A4 (in), 5 A3 (in), 6 A2 (in), 7 A1 (in), 8 A0 (in), 9 D0 (hiz), 10 D1 (hiz), 11 D2 (hiz), 12 GND (power) hidden to GND, 13 D3 (hiz), 14 D4 (hiz), 15 D5 (hiz), 16 D6 (hiz), 17 D7 (hiz), 18 ~{E}/P (in), 19 A10 (in), 20 ~{OE} (in), 21 VPP (in), 22 A9 (in), 23 A8 (in), 24 VCC (power) hidden to VCC
2 alternate drawings of the same symbol

## 2732
designator U?
footprint DIP-24
pins: 1 A7 (in), 2 A6 (in), 3 A5 (in), 4 A4 (in), 5 A3 (in), 6 A2 (in), 7 A1 (in), 8 A0 (in), 9 D0 (hiz), 10 D1 (hiz), 11 D2 (hiz), 12 GND (power) hidden to GND, 13 D3 (hiz), 14 D4 (hiz), 15 D5 (hiz), 16 D6 (hiz), 17 D7 (hiz), 18 ~{CE} (in), 19 A10 (in), 20 ~{OE}/VPP (in), 21 A11 (in), 22 A9 (in), 23 A8 (in), 24 VCC (power) hidden to VCC
2 alternate drawings of the same symbol

## 2764
designator U?
footprint DIP-28
pins: 1 VPP (in), 2 A12 (in), 3 A7 (in), 4 A6 (in), 5 A5 (in), 6 A4 (in), 7 A3 (in), 8 A2 (in), 9 A1 (in), 10 A0 (in), 11 D0 (hiz), 12 D1 (hiz), 13 D2 (hiz), 14 GND (power) hidden to GND, 15 D3 (hiz), 16 D4 (hiz), 17 D5 (hiz), 18 D6 (hiz), 19 D7 (hiz), 20 ~{CE} (in), 21 A10 (in), 22 ~{OE} (in), 23 A11 (in), 24 A9 (in), 25 A8 (in), 27 ~{PGM} (in), 28 VCC (power) hidden to VCC
2 alternate drawings of the same symbol

## 4164
designator U?
footprint DIP-16
pins: 2 Q (in), 3 ~{W} (in), 4 ~{RAS} (in), 5 A0 (in), 6 A2 (in), 7 A1 (in), 8 VCC (power) hidden to VCC, 9 A7 (in), 10 A5 (in), 11 A4 (in), 12 A3 (in), 13 A6 (in), 14 D (hiz), 15 ~{CAS} (in), 16 GND (power) hidden to GND
2 alternate drawings of the same symbol

## 4416
designator U?
footprint DIP-18
pins: 1 ~{OE} (in), 4 ~{WE} (in), 5 ~{RAS} (in), 6 A6 (in), 7 A5 (in), 8 A4 (in), 9 VCC (power) hidden to VCC, 10 A7 (in), 11 A3 (in), 11 D3 (hiz), 12 A2 (in), 12 D2 (hiz), 13 A1 (in), 13 D1 (hiz), 14 A0 (in), 14 D0 (hiz), 16 ~{CAS} (in), 18 GND (power) hidden to GND
2 alternate drawings of the same symbol

## 6116
designator U?
footprint DIP-24
pins: 1 A7 (in), 2 A6 (in), 3 A5 (in), 4 A4 (in), 5 A3 (in), 6 A2 (in), 7 A1 (in), 8 A0 (in), 9 D0 (hiz), 10 D1 (hiz), 11 D2 (hiz), 12 GND (power) hidden to GND, 13 D3 (hiz), 14 D4 (hiz), 15 D5 (hiz), 16 D6 (hiz), 17 D7 (hiz), 18 ~{E} (in), 19 A10 (in), 20 ~{G} (in), 21 ~{W} (in), 22 A9 (in), 23 A8 (in), 24 VCC (power) hidden to VCC
2 alternate drawings of the same symbol

## 6164
designator U?
footprint DIP-28
pins: 2 A12 (in), 3 A7 (in), 4 A6 (in), 5 A5 (in), 6 A4 (in), 7 A3 (in), 8 A2 (in), 9 A1 (in), 10 A0 (in), 11 D0 (hiz), 12 D1 (hiz), 13 D2 (hiz), 14 GND (power) hidden to GND, 15 D3 (hiz), 16 D4 (hiz), 17 D5 (hiz), 18 D6 (hiz), 19 D7 (hiz), 20 ~{CS1} (in), 21 A10 (in), 22 ~{OE} (in), 23 A11 (in), 24 A9 (in), 25 A8 (in), 26 CS2 (in), 27 ~{WE} (in), 28 VCC (power) hidden to VCC
2 alternate drawings of the same symbol

## 6664
designator U?
footprint DIP-16
pins: 1 ~{RFSH} (in), 2 Q (in), 3 ~{W} (in), 4 ~{RAS} (in), 5 A0 (in), 6 A2 (in), 7 A1 (in), 8 VCC (power) hidden to VCC, 9 A7 (in), 10 A5 (in), 11 A4 (in), 12 A3 (in), 13 A6 (in), 14 D (hiz), 15 ~{CAS} (in), 16 GND (power) hidden to GND
2 alternate drawings of the same symbol

## 27128
designator U?
footprint DIP-28
pins: 1 VPP (in), 2 A12 (in), 3 A7 (in), 4 A6 (in), 5 A5 (in), 6 A4 (in), 7 A3 (in), 8 A2 (in), 9 A1 (in), 10 A0 (in), 11 D0 (hiz), 12 D1 (hiz), 13 D2 (hiz), 14 GND (power) hidden to GND, 15 D3 (hiz), 16 D4 (hiz), 17 D5 (hiz), 18 D6 (hiz), 19 D7 (hiz), 20 ~{CE} (in), 21 A10 (in), 22 ~{OE} (in), 23 A11 (in), 24 A9 (in), 25 A8 (in), 26 A13 (in), 27 ~{PGM} (in), 28 VCC (power) hidden to VCC
2 alternate drawings of the same symbol

## 27256
designator U?
footprint DIP-28
footprint DIP28-O
pins: 1 VPP (in), 2 A12 (in), 3 A7 (in), 4 A6 (in), 5 A5 (in), 6 A4 (in), 7 A3 (in), 8 A2 (in), 9 A1 (in), 10 A0 (in), 11 D0 (hiz), 12 D1 (hiz), 13 D2 (hiz), 14 GND (power) hidden to GND, 15 D3 (hiz), 16 D4 (hiz), 17 D5 (hiz), 18 D6 (hiz), 19 D7 (hiz), 20 ~{CE} (in), 21 A10 (in), 22 ~{OE} (in), 23 A11 (in), 24 A9 (in), 25 A8 (in), 26 A13 (in), 27 A14 (in), 28 VCC (power) hidden to VCC
2 alternate drawings of the same symbol

## 27512
designator U?
footprint DIP-28
pins: 1 A15 (in), 2 A12 (in), 3 A7 (in), 4 A6 (in), 5 A5 (in), 6 A4 (in), 7 A3 (in), 8 A2 (in), 9 A1 (in), 10 A0 (in), 11 D0 (hiz), 12 D1 (hiz), 13 D2 (hiz), 14 GND (power) hidden to GND, 15 D3 (hiz), 16 D4 (hiz), 17 D5 (hiz), 18 D6 (hiz), 19 D7 (hiz), 20 ~{CE} (in), 21 A10 (in), 22 ~{OE} (in), 23 A11 (in), 24 A9 (in), 25 A8 (in), 26 A13 (in), 27 A14 (in), 28 VCC (power) hidden to VCC
2 alternate drawings of the same symbol

## 41256
designator U?
footprint DIP-16
pins: 1 A8 (in), 2 D (in), 3 ~{WE} (in), 4 ~{RAS} (in), 5 A0 (in), 6 A2 (in), 7 A1 (in), 8 VCC (power) hidden to VCC, 9 A7 (in), 10 A5 (in), 11 A4 (in), 12 A3 (in), 13 A6 (in), 14 Q (hiz), 15 ~{CAS} (in), 16 GND (power) hidden to GND
2 alternate drawings of the same symbol

## 76165
designator U?
footprint DIP-20
pins: 1 A8 (in), 2 A7 (in), 3 A6 (in), 4 A5 (in), 5 A4 (in), 6 A3 (in), 7 A2 (in), 8 A1 (in), 9 A0 (in), 10 GND (power) hidden to GND, 11 Q4 (hiz), 12 Q3 (hiz), 13 Q2 (hiz), 14 Q1 (hiz), 15 ~{E2} (in), 16 ~{E1} (in), 17 A11 (in), 18 A10 (in), 19 A9 (in), 20 VCC (power) hidden to VCC
2 alternate drawings of the same symbol

## 76641
designator U?
footprint DIP-24
pins: 1 A7 (in), 2 A6 (in), 3 A5 (in), 4 A4 (in), 5 A3 (in), 6 A2 (in), 7 A1 (in), 8 A0 (in), 9 Q1 (hiz), 10 Q2 (hiz), 11 Q3 (hiz), 12 GND (power) hidden to GND, 13 Q4 (hiz), 14 Q5 (hiz), 15 Q6 (hiz), 16 Q7 (hiz), 17 Q8 (hiz), 18 A12 (in), 19 A11 (in), 20 ~{E} (in), 21 A10 (in), 22 A9 (in), 23 A8 (in), 24 VCC (power) hidden to VCC
2 alternate drawings of the same symbol


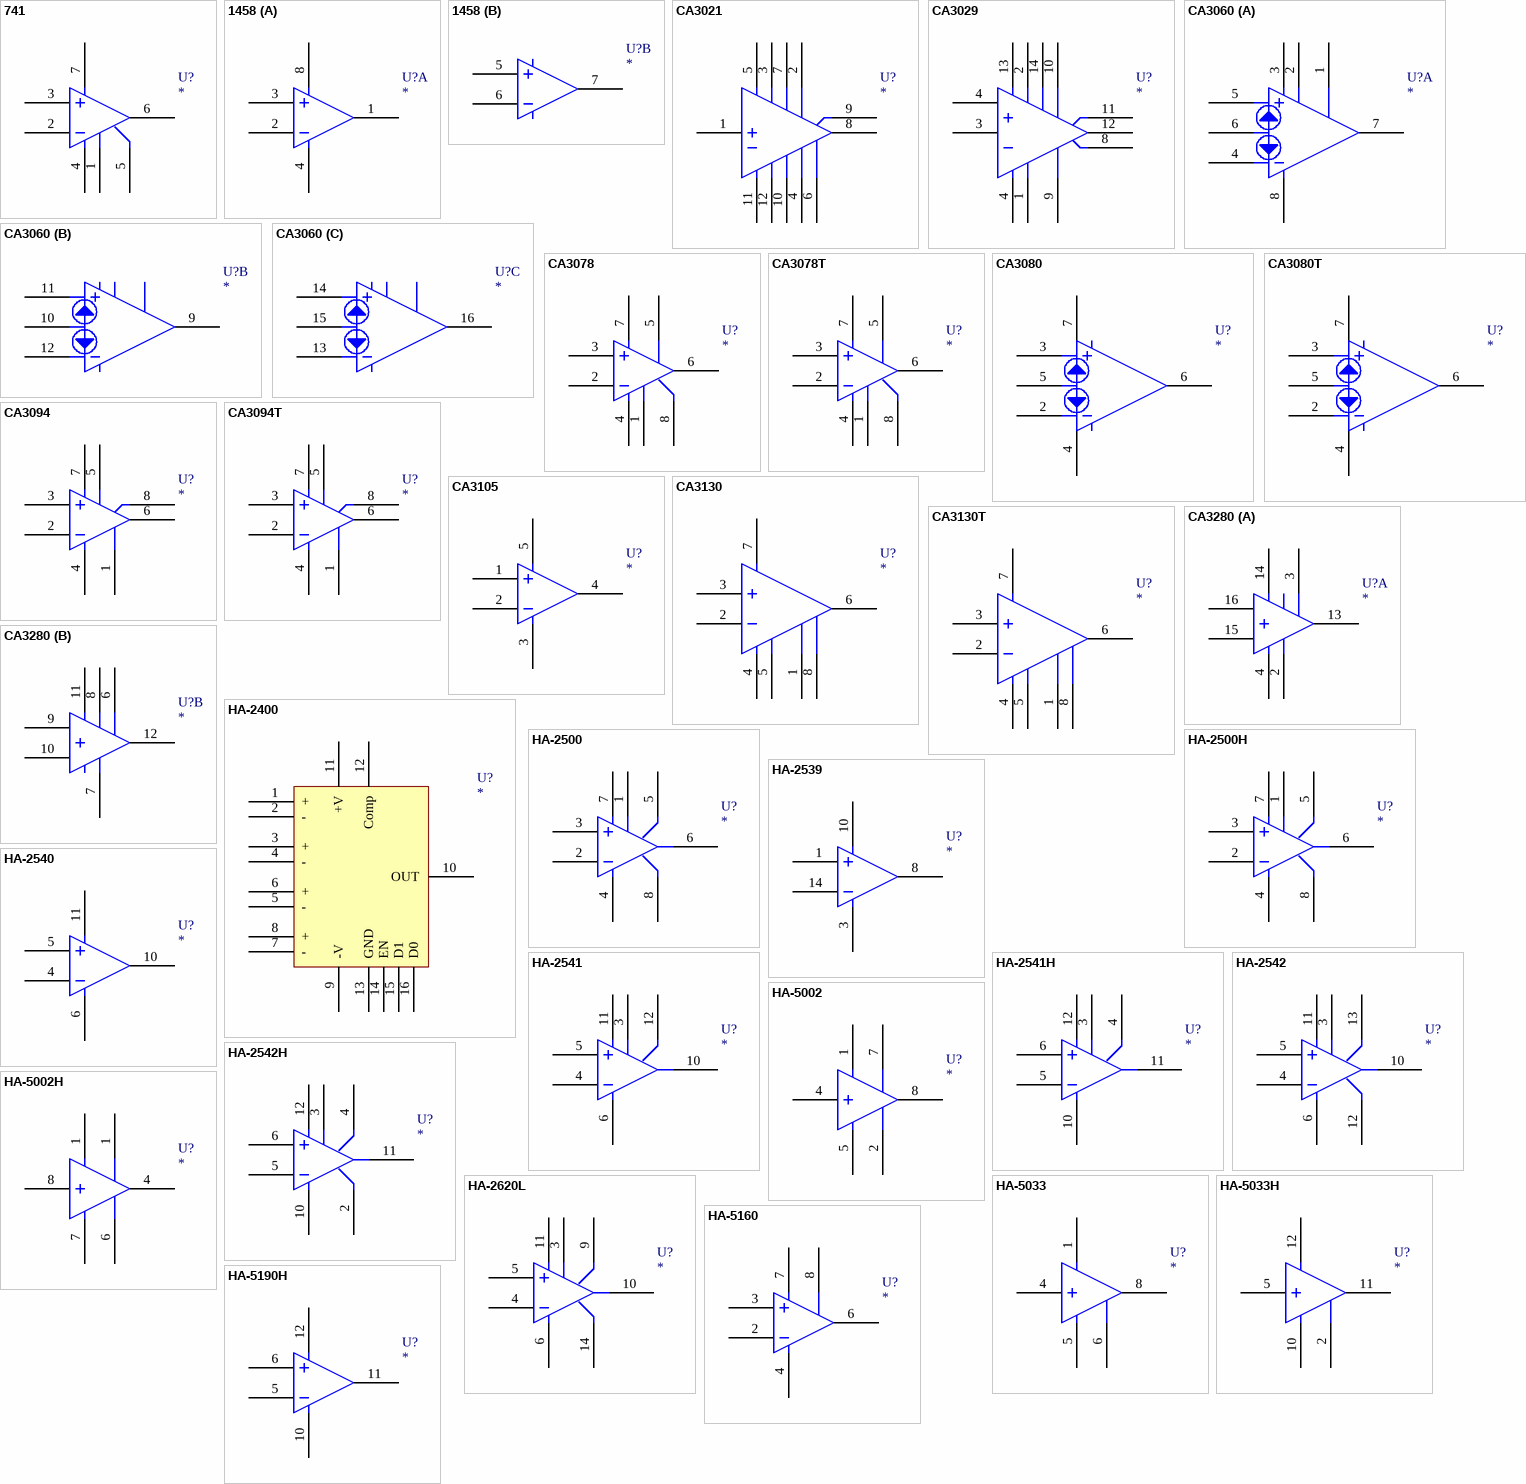
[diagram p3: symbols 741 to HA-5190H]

## 741
designator U?
footprint DIP8E
pins: 1, 2, 3, 4, 5, 6, 7
2 alternate drawings of the same symbol

## 1458
designator U?
footprint DIP8E
part A pins: 1, 2, 3, 4, 8
part B pins: 5, 6, 7
2 alternate drawings of the same symbol

## CA3021
designator U?
footprint METAL12
pins: 1, 2, 3, 4, 5, 6, 7, 8, 9, 10, 11, 12
2 alternate drawings of the same symbol

## CA3029
designator U?
footprint DIP-14
pins: 1, 2, 3, 4, 4, 8, 9, 10, 11, 12, 13, 14
2 alternate drawings of the same symbol

## CA3060
designator U?
footprint DIP-16
part A pins: 1, 2, 3, 4, 5, 6, 7, 8
part B pins: 9, 10, 11, 12
part C pins: 13, 14, 15, 16
2 alternate drawings of the same symbol

## CA3078
designator U?
footprint DIP-8
pins: 1, 2, 3, 4, 5, 6, 7, 8
2 alternate drawings of the same symbol

## CA3078T
designator U?
footprint METAL8
pins: 1, 2, 3, 4, 5, 6, 7, 8
2 alternate drawings of the same symbol

## CA3080
designator U?
footprint DIP-8
pins: 2, 3, 4, 5, 6, 7
2 alternate drawings of the same symbol

## CA3080T
designator U?
footprint METAL8
pins: 2, 3, 4, 5, 6, 7
2 alternate drawings of the same symbol

## CA3094
designator U?
footprint DIP-8
pins: 1, 2, 3, 4, 5, 6, 7, 8
2 alternate drawings of the same symbol

## CA3094T
designator U?
footprint METAL8
pins: 1, 2, 3, 4, 5, 6, 7, 8
2 alternate drawings of the same symbol

## CA3105
designator U?
footprint TO-220-5S
pins: 1, 2, 3, 4, 5
2 alternate drawings of the same symbol

## CA3130
designator U?
footprint DIP8E
pins: 1, 2, 3, 4, 5, 6, 7, 8
2 alternate drawings of the same symbol

## CA3130T
designator U?
footprint METAL8
pins: 1, 2, 3, 4, 5, 6, 7, 8
2 alternate drawings of the same symbol

## CA3280
designator U?
footprint DIP-16
part A pins: 1, 2, 3, 4, 13, 14, 15, 16
part B pins: 6, 7, 8, 9, 10, 11, 12
2 alternate drawings of the same symbol

## HA-2400
designator U?
footprint DIP-16
pins: 1 +, 2 -, 3 +, 4 -, 5 -, 6 +, 7 -, 8 +, 9 -V, 10 OUT, 11 +V, 12 Comp, 13 GND, 14 EN, 15 D1, 16 D0
2 alternate drawings of the same symbol

## HA-2500
designator U?
footprint DIP-8
pins: 1, 2, 3, 4, 5, 6, 7, 8
2 alternate drawings of the same symbol

## HA-2500H
designator U?
footprint METAL8
pins: 1, 2, 3, 4, 5, 6, 7, 8
2 alternate drawings of the same symbol

## HA-2539
designator U?
footprint DIP-14
pins: 1, 3, 8, 10, 14
2 alternate drawings of the same symbol

## HA-2540
designator U?
footprint DIP-14
pins: 4, 5, 6, 10, 11
2 alternate drawings of the same symbol

## HA-2541
designator U?
footprint DIP-14
pins: 3, 4, 5, 6, 10, 11, 12
2 alternate drawings of the same symbol

## HA-2541H
designator U?
footprint METAL12
pins: 3, 4, 5, 6, 10, 11, 12
2 alternate drawings of the same symbol

## HA-2542
designator U?
footprint DIP-14
pins: 3, 4, 5, 6, 10, 11, 12, 13
2 alternate drawings of the same symbol

## HA-2542H
designator U?
footprint METAL12
pins: 2, 3, 4, 5, 6, 10, 11, 12
2 alternate drawings of the same symbol

## HA-2620L
designator U?
footprint DIP-14
pins: 3, 4, 5, 6, 9, 10, 11, 14
2 alternate drawings of the same symbol

## HA-5002
designator U?
footprint DIP-8
pins: 1, 2, 4, 5, 7, 8
2 alternate drawings of the same symbol

## HA-5002H
designator U?
footprint METAL8
pins: 1, 1, 4, 6, 7, 8
2 alternate drawings of the same symbol

## HA-5033
designator U?
footprint DIP-8
pins: 1, 4, 5, 6, 8
2 alternate drawings of the same symbol

## HA-5033H
designator U?
footprint METAL12
pins: 2, 5, 10, 11, 12
2 alternate drawings of the same symbol

## HA-5160
designator U?
footprint METAL8
pins: 2, 3, 4, 6, 7, 8
2 alternate drawings of the same symbol

## HA-5190H
designator U?
footprint METAL12
pins: 5, 6, 10, 11, 12
2 alternate drawings of the same symbol

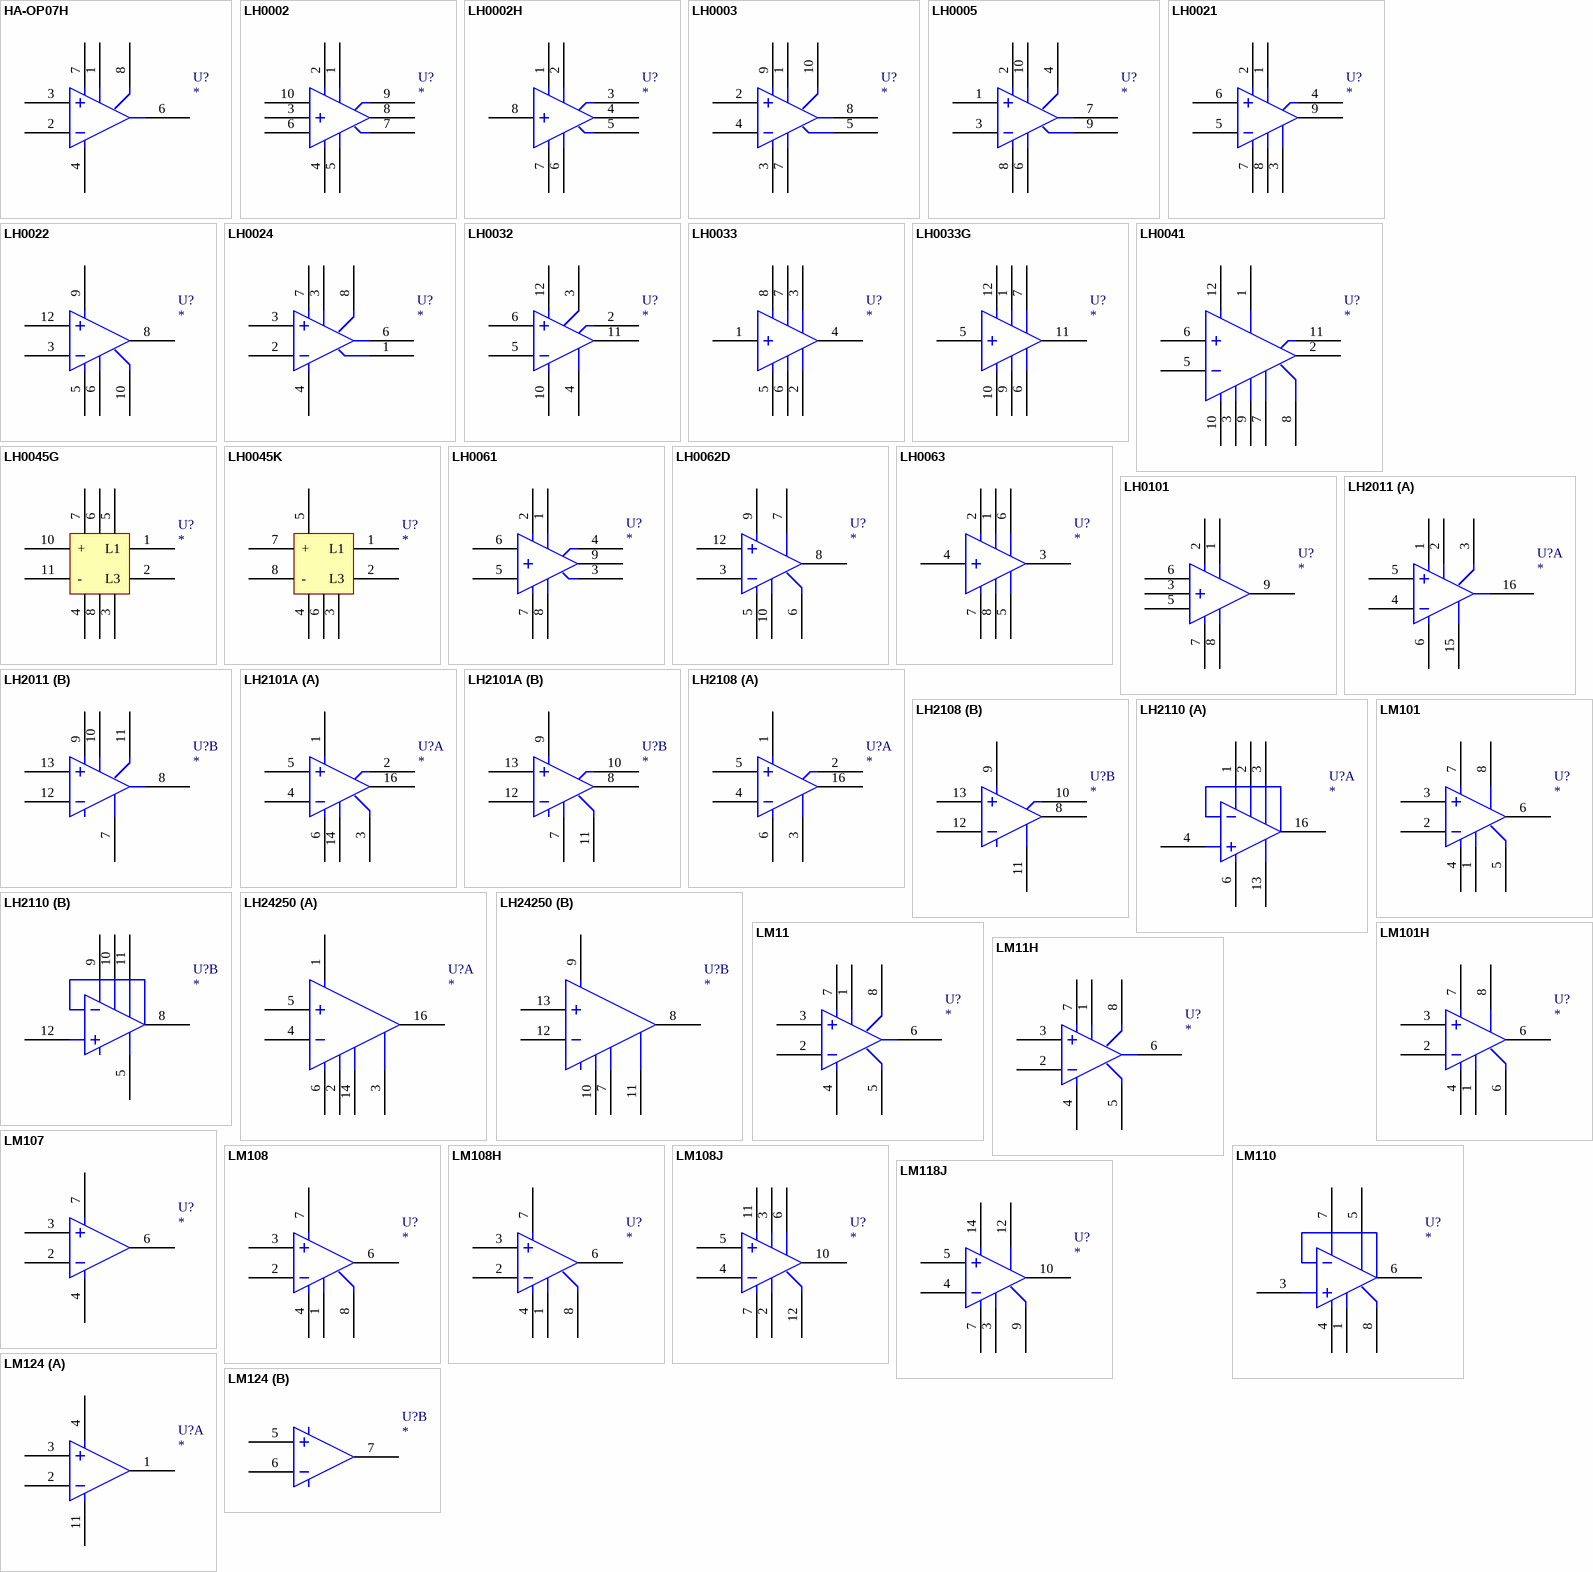
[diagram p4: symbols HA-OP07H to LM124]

## HA-OP07H
designator U?
footprint METAL8
pins: 1, 2, 3, 4, 6, 7, 8
2 alternate drawings of the same symbol

## LH0002
designator U?
footprint DIP-10
pins: 1, 2, 3, 4, 5, 6, 7, 8, 9, 10
2 alternate drawings of the same symbol

## LH0002H
designator U?
footprint METAL8
pins: 1, 2, 3, 4, 5, 6, 7, 8
2 alternate drawings of the same symbol

## LH0003
designator U?
footprint METAL10
pins: 1, 2, 3, 4, 5, 7, 8, 9, 10
2 alternate drawings of the same symbol

## LH0005
designator U?
footprint METAL10
pins: 1, 2, 3, 4, 6, 7, 8, 9, 10
2 alternate drawings of the same symbol

## LH0021
designator U?
footprint TO-3
pins: 1, 2, 3, 4, 5, 6, 7, 8, 9
2 alternate drawings of the same symbol

## LH0022
designator U?
footprint DIP-14
pins: 3, 5, 6, 8, 9, 10, 12
2 alternate drawings of the same symbol

## LH0024
designator U?
footprint METAL8
pins: 1, 2, 3, 3, 4, 6, 7, 8
2 alternate drawings of the same symbol

## LH0032
designator U?
footprint METAL12
pins: 2, 3, 4, 5, 6, 10, 11, 12
2 alternate drawings of the same symbol

## LH0033
designator U?
footprint DIP-8
pins: 1, 2, 3, 4, 5, 6, 7, 8
2 alternate drawings of the same symbol

## LH0033G
designator U?
footprint METAL12
pins: 1, 5, 6, 7, 9, 10, 11, 12
2 alternate drawings of the same symbol

## LH0041
designator U?
footprint METAL12
pins: 1, 2, 3, 5, 6, 7, 8, 9, 10, 11, 12
2 alternate drawings of the same symbol

## LH0045G
designator U?
footprint METAL12
pins: 1 L1, 2 L3, 3, 4, 5, 6, 7, 8, 10 +, 11 -
2 alternate drawings of the same symbol

## LH0045K
designator U?
footprint TO-3
pins: 1 L1, 2 L3, 3, 4, 5, 6, 7 +, 8 -
2 alternate drawings of the same symbol

## LH0061
designator U?
footprint TO-3
pins: 1, 2, 3, 4, 5, 6, 7, 8, 9
2 alternate drawings of the same symbol

## LH0062D
designator U?
footprint DIP-14
pins: 3, 5, 6, 7, 8, 9, 10, 12
2 alternate drawings of the same symbol

## LH0063
designator U?
footprint TO-3
pins: 1, 2, 3, 4, 5, 6, 7, 8
2 alternate drawings of the same symbol

## LH0101
designator U?
footprint TO-3
pins: 1, 2, 3, 5, 6, 7, 8, 9
2 alternate drawings of the same symbol

## LH2011
designator U?
footprint DIP-16
part A pins: 1, 2, 3, 4, 5, 6, 15, 16
part B pins: 7, 8, 9, 10, 11, 12, 13
2 alternate drawings of the same symbol

## LH2101A
designator U?
footprint DIP-16
part A pins: 1, 2, 3, 4, 5, 6, 14, 16
part B pins: 7, 8, 9, 10, 11, 12, 13
2 alternate drawings of the same symbol

## LH2108
designator U?
footprint DIP-16
part A pins: 1, 2, 3, 4, 5, 6, 16
part B pins: 8, 9, 10, 11, 12, 13
2 alternate drawings of the same symbol

## LH2110
designator U?
footprint DIP-16
part A pins: 1, 2, 3, 4, 6, 13, 16
part B pins: 5, 8, 9, 10, 11, 12
2 alternate drawings of the same symbol

## LH24250
designator U?
footprint DIP-16
part A pins: 1, 2, 3, 4, 5, 6, 14, 16
part B pins: 7, 8, 9, 10, 11, 12, 13
2 alternate drawings of the same symbol

## LM11
designator U?
footprint DIP-8
pins: 1, 2, 3, 4, 5, 6, 7, 8
2 alternate drawings of the same symbol

## LM11H
designator U?
footprint METAL8
pins: 1, 2, 3, 4, 5, 6, 7, 8
2 alternate drawings of the same symbol

## LM101
designator U?
footprint DIP-8
pins: 1, 2, 3, 4, 5, 6, 7, 8
2 alternate drawings of the same symbol

## LM101H
designator U?
footprint METAL8
pins: 1, 2, 3, 4, 6, 6, 7, 8
2 alternate drawings of the same symbol

## LM107
designator U?
footprint DIP-8
pins: 2, 3, 4, 6, 7
2 alternate drawings of the same symbol

## LM108
designator U?
footprint DIP-8
pins: 1, 2, 3, 4, 6, 7, 8
2 alternate drawings of the same symbol

## LM108H
designator U?
footprint METAL8
pins: 1, 2, 3, 4, 6, 7, 8
2 alternate drawings of the same symbol

## LM108J
designator U?
footprint DIP-14
pins: 2, 3, 4, 5, 6, 7, 10, 11, 12
2 alternate drawings of the same symbol

## LM110
designator U?
footprint DIP-8
pins: 1, 3, 4, 5, 6, 7, 8
2 alternate drawings of the same symbol

## LM118J
designator U?
footprint DIP-14
pins: 3, 4, 5, 7, 9, 10, 12, 14
2 alternate drawings of the same symbol

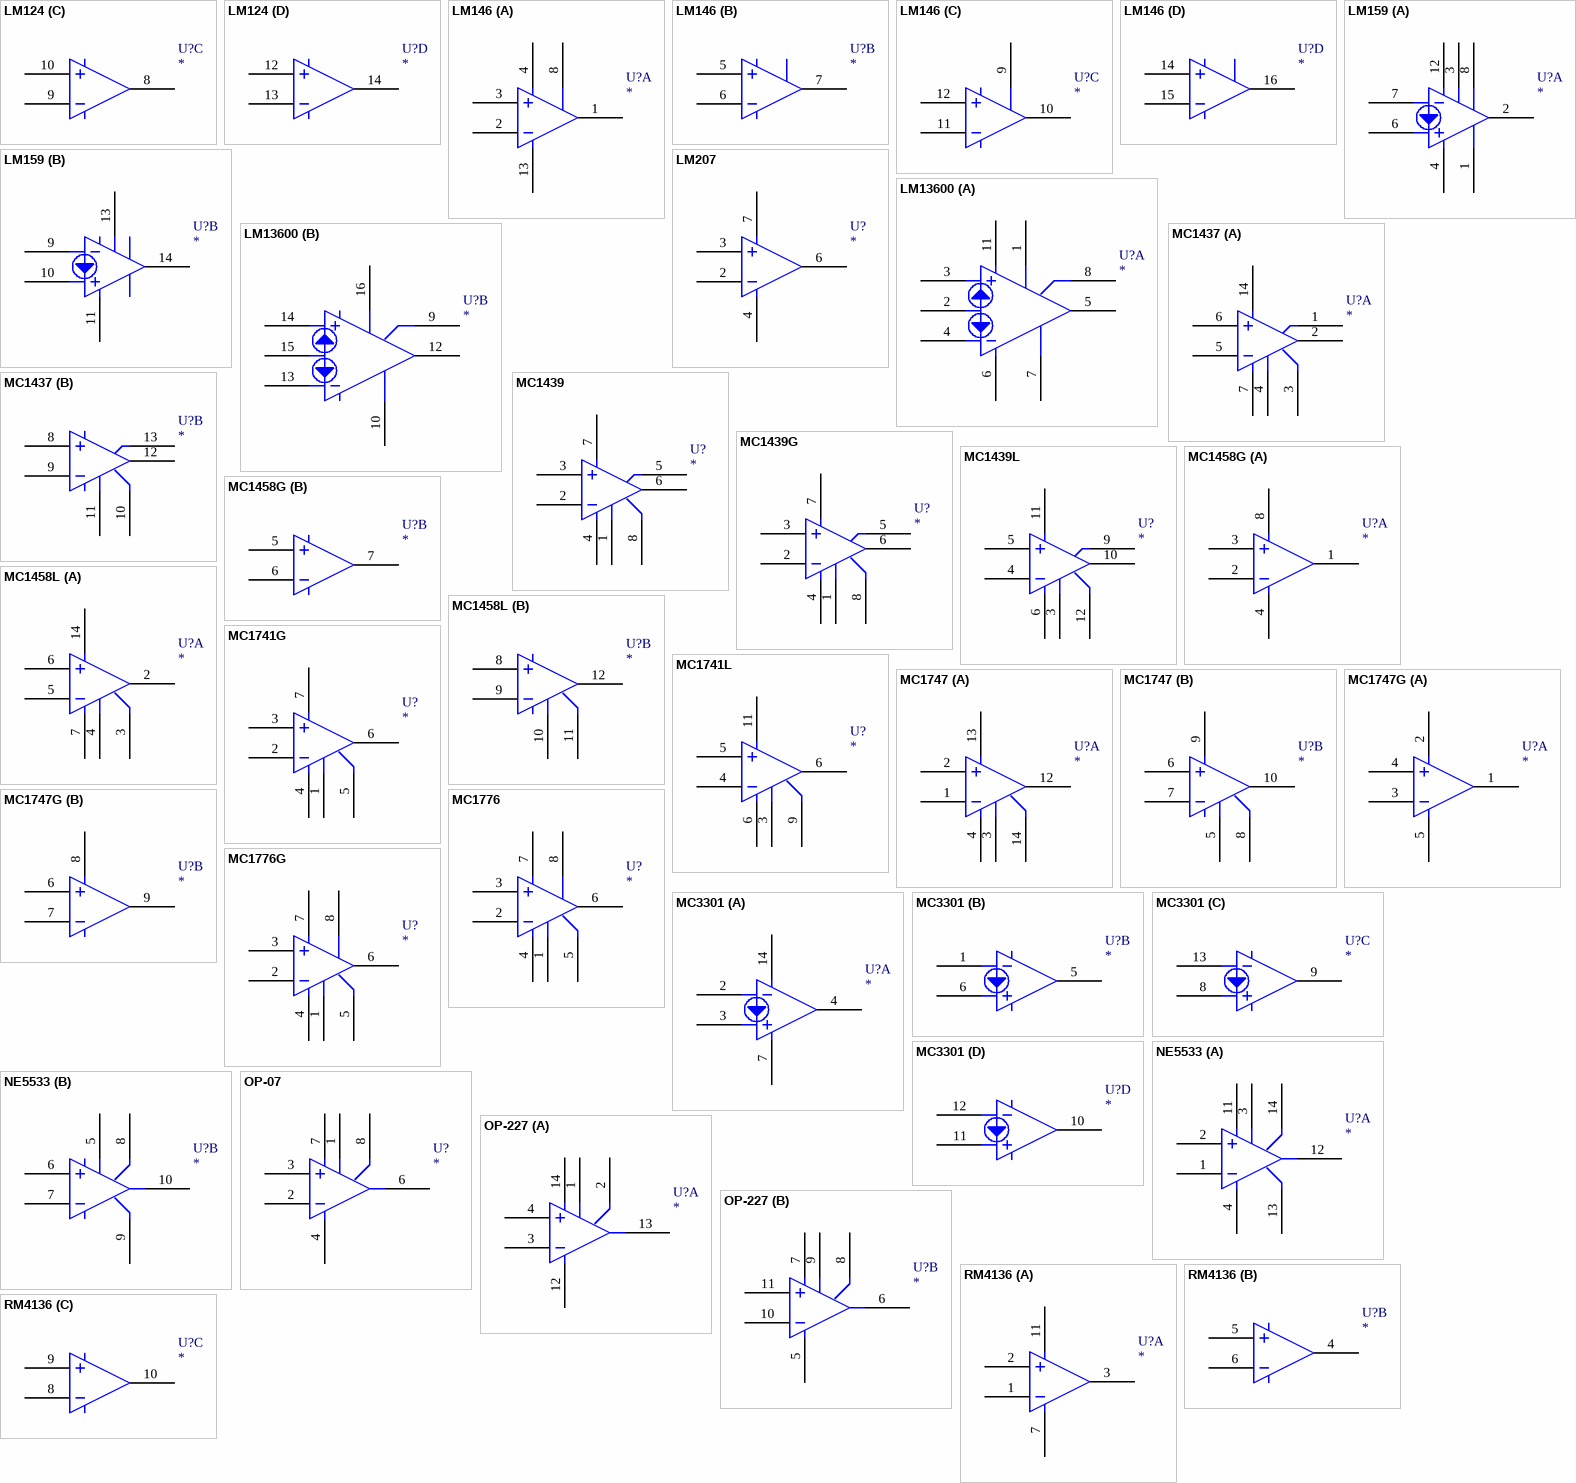
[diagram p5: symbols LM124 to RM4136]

## LM124
designator U?
footprint DIP-14
footprint DIP14E
part A pins: 1, 2, 3, 4, 11
part B pins: 5, 6, 7
part C pins: 8, 9, 10
part D pins: 12, 13, 14
2 alternate drawings of the same symbol

## LM146
designator U?
footprint DIP-16
part A pins: 1, 2, 3, 4, 8, 13
part B pins: 5, 6, 7
part C pins: 9, 10, 11, 12
part D pins: 14, 15, 16
2 alternate drawings of the same symbol

## LM159
designator U?
footprint DIP-14
part A pins: 1, 2, 3, 4, 6, 7, 8, 12
part B pins: 9, 10, 11, 13, 14
2 alternate drawings of the same symbol

## LM207
designator U?
footprint METAL8
pins: 2, 3, 4, 6, 7
2 alternate drawings of the same symbol

## LM13600
designator U?
footprint DIP-16
part A pins: 1, 2, 3, 4, 5, 6, 7, 8, 11
part B pins: 9, 10, 12, 13, 14, 15, 16
2 alternate drawings of the same symbol

## MC1437
designator U?
footprint DIP-14
part A pins: 1, 2, 3, 4, 5, 6, 7, 14
part B pins: 8, 9, 10, 11, 12, 13
2 alternate drawings of the same symbol

## MC1439
designator U?
footprint DIP-8
pins: 1, 2, 3, 4, 5, 6, 7, 8
2 alternate drawings of the same symbol

## MC1439G
designator U?
footprint METAL8
pins: 1, 2, 3, 4, 5, 6, 7, 8
2 alternate drawings of the same symbol

## MC1439L
designator U?
footprint DIP-14
pins: 3, 4, 5, 6, 9, 10, 11, 12
2 alternate drawings of the same symbol

## MC1458G
designator U?
footprint METAL8
part A pins: 1, 2, 3, 4, 8
part B pins: 5, 6, 7
2 alternate drawings of the same symbol

## MC1458L
designator U?
footprint DIP14E
part A pins: 2, 3, 4, 5, 6, 7, 14
part B pins: 8, 9, 10, 11, 12
2 alternate drawings of the same symbol

## MC1741G
designator U?
footprint METAL8
pins: 1, 2, 3, 4, 5, 6, 7
2 alternate drawings of the same symbol

## MC1741L
designator U?
footprint DIP-14
pins: 3, 4, 5, 6, 6, 9, 11
2 alternate drawings of the same symbol

## MC1747
designator U?
footprint DIP-14
part A pins: 1, 2, 3, 4, 12, 13, 14
part B pins: 5, 6, 7, 8, 9, 10
2 alternate drawings of the same symbol

## MC1747G
designator U?
footprint METAL10
part A pins: 1, 2, 3, 4, 5
part B pins: 6, 7, 8, 9
2 alternate drawings of the same symbol

## MC1776
designator U?
footprint DIP-8
pins: 1, 2, 3, 4, 5, 6, 7, 8
2 alternate drawings of the same symbol

## MC1776G
designator U?
footprint METAL8
pins: 1, 2, 3, 4, 5, 6, 7, 8
2 alternate drawings of the same symbol

## MC3301
designator U?
footprint DIP-14
part A pins: 2, 3, 4, 7, 14
part B pins: 1, 5, 6
part C pins: 8, 9, 13
part D pins: 10, 11, 12
2 alternate drawings of the same symbol

## NE5533
designator U?
footprint DIP-14
part A pins: 1, 2, 3, 4, 11, 12, 13, 14
part B pins: 5, 6, 7, 8, 9, 10
2 alternate drawings of the same symbol

## OP-07
designator U?
footprint DIP8E
pins: 1, 2, 3, 4, 6, 7, 8
2 alternate drawings of the same symbol

## OP-227
designator U?
footprint DIP-14
part A pins: 1, 2, 3, 4, 12, 13, 14
part B pins: 5, 6, 7, 8, 9, 10, 11
2 alternate drawings of the same symbol

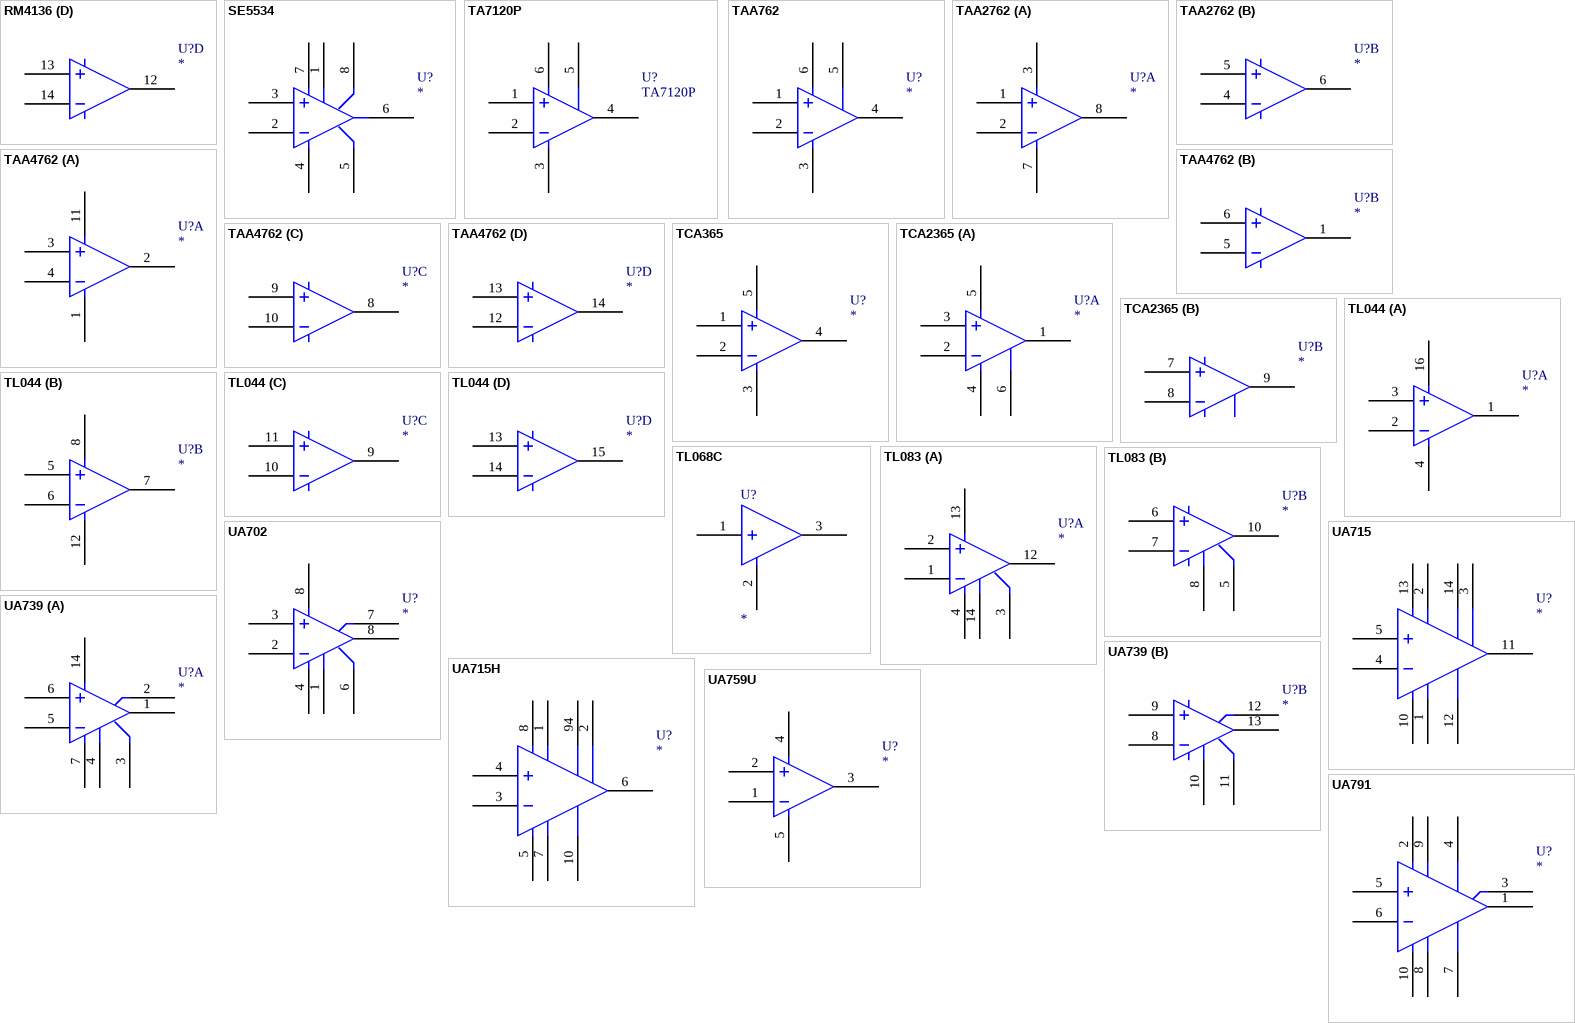
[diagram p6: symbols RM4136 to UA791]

## RM4136
designator U?
footprint DIP-14
part A pins: 1, 2, 3, 7, 11
part B pins: 4, 5, 6
part C pins: 8, 9, 10
part D pins: 12, 13, 14
2 alternate drawings of the same symbol

## SE5534
designator U?
footprint DIP-8
pins: 1, 2, 3, 4, 5, 6, 7, 8
2 alternate drawings of the same symbol

## TA7120P
designator U?
footprint DIP8E
pins: 1, 2, 3, 4, 5, 6
2 alternate drawings of the same symbol

## TAA762
designator U?
footprint DIP-6
pins: 1, 2, 3, 4, 5, 6
2 alternate drawings of the same symbol

## TAA2762
designator U?
footprint DIP-8
part A pins: 1, 2, 3, 7, 8
part B pins: 4, 5, 6
2 alternate drawings of the same symbol

## TAA4762
designator U?
footprint DIP-14
part A pins: 1, 2, 3, 4, 11
part B pins: 1, 5, 6
part C pins: 8, 9, 10
part D pins: 12, 13, 14
2 alternate drawings of the same symbol

## TCA365
designator U?
footprint TO-220-5S
pins: 1, 2, 3, 4, 5
2 alternate drawings of the same symbol

## TCA2365
designator U?
footprint SIP9
part A pins: 1, 2, 3, 4, 5, 6
part B pins: 7, 8, 9
2 alternate drawings of the same symbol

## TL044
designator U?
footprint DIP-16
part A pins: 1, 2, 3, 4, 16
part B pins: 5, 6, 7, 8, 12
part C pins: 9, 10, 11
part D pins: 13, 14, 15
2 alternate drawings of the same symbol

## TL068C
designator U?
footprint TO-92A
pins: 1, 2, 3
2 alternate drawings of the same symbol

## TL083
designator U?
footprint DIP-14
part A pins: 1, 2, 3, 4, 12, 13, 14
part B pins: 5, 6, 7, 8, 10
2 alternate drawings of the same symbol

## UA702
designator U?
footprint DIP-8
pins: 1, 2, 3, 4, 6, 7, 8, 8
2 alternate drawings of the same symbol

## UA715
designator U?
footprint DIP-14
pins: 1, 2, 3, 4, 5, 10, 11, 12, 13, 14
2 alternate drawings of the same symbol

## UA715H
designator U?
footprint METAL10
pins: 1, 2, 3, 4, 5, 6, 7, 8, 10, 94
2 alternate drawings of the same symbol

## UA739
designator U?
footprint DIP-14
part A pins: 1, 2, 3, 4, 5, 6, 7, 14
part B pins: 8, 9, 10, 11, 12, 13
2 alternate drawings of the same symbol

## UA759U
designator U?
footprint MOLDED4
pins: 1, 2, 3, 4, 5
2 alternate drawings of the same symbol

## UA791
designator U?
footprint METAL10
pins: 1, 2, 3, 4, 5, 6, 7, 8, 9, 10
2 alternate drawings of the same symbol


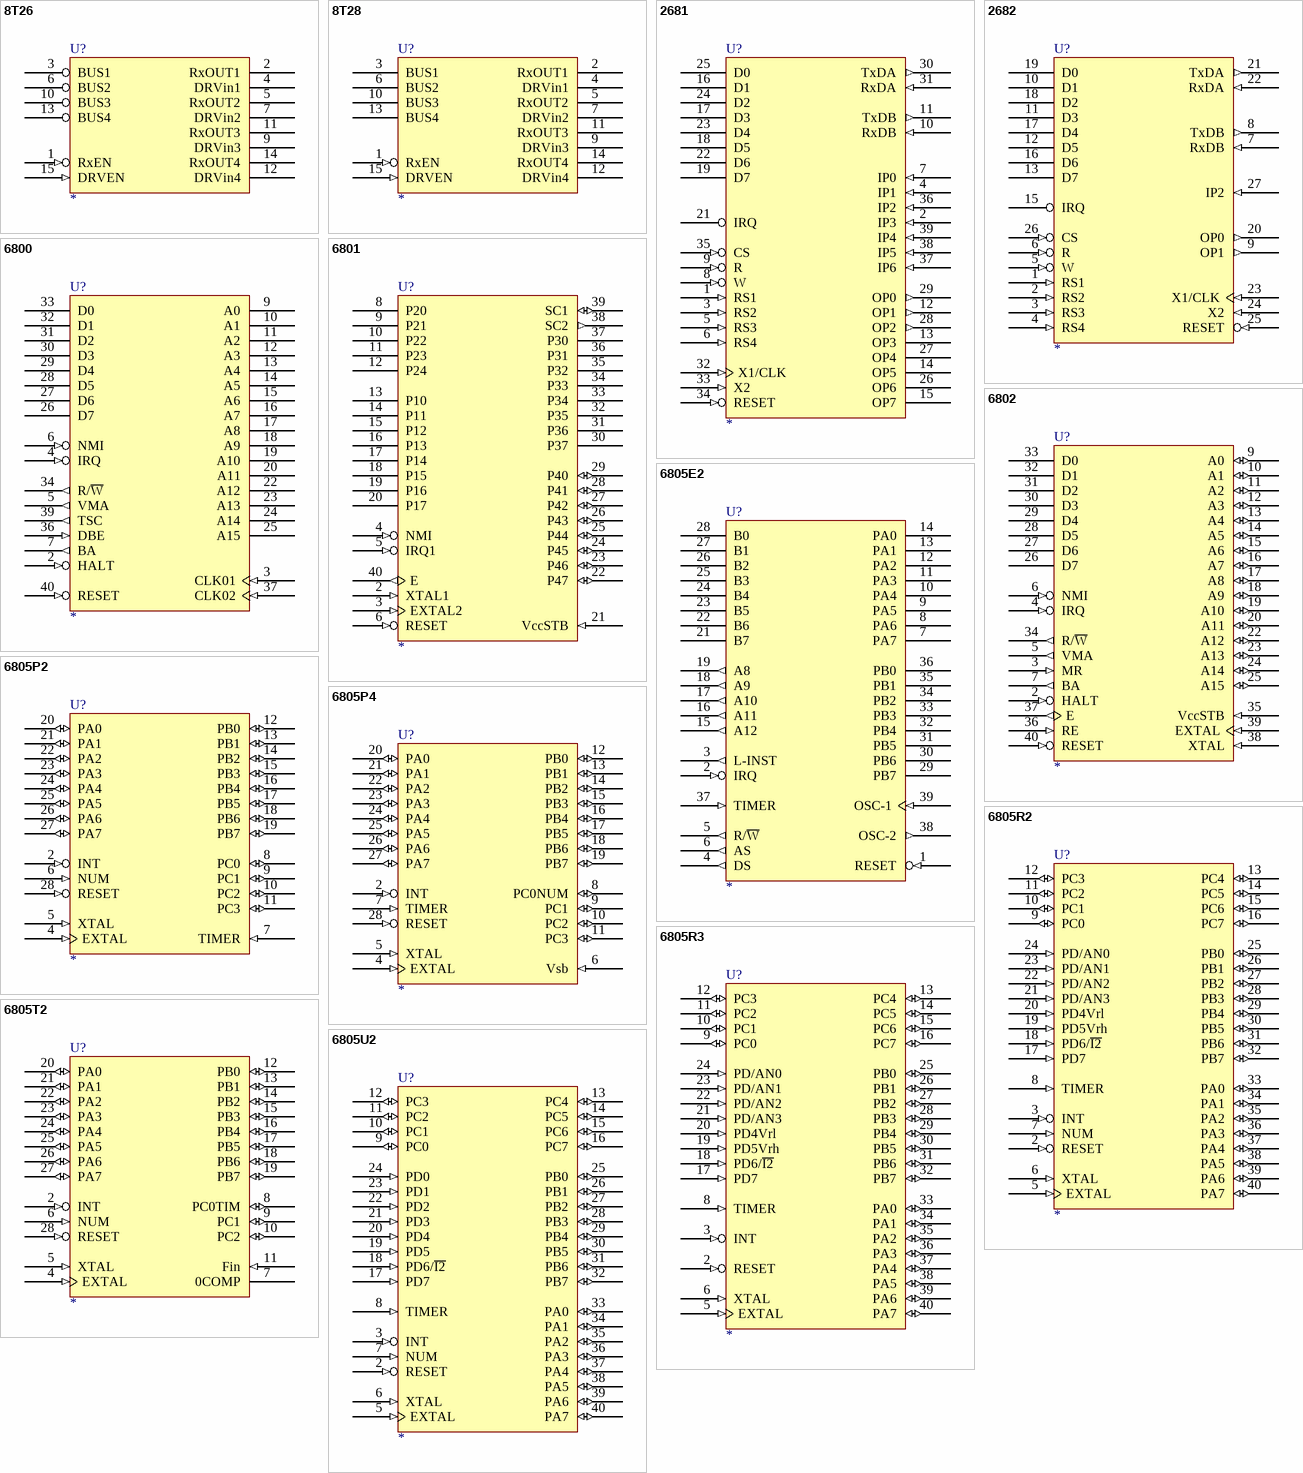
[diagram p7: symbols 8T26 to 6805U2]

## 8T26
designator U?
footprint DIP-16
pins: 1 RxEN (in), 2 RxOUT1 (hiz), 3 BUS1 (hiz), 4 DRVin1 (hiz), 5 RxOUT2 (hiz), 6 BUS2 (hiz), 7 DRVin2 (hiz), 8 GND (power) hidden to GND, 9 DRVin3 (hiz), 10 BUS3 (hiz), 11 RxOUT3 (hiz), 12 DRVin4 (hiz), 13 BUS4 (hiz), 14 RxOUT4 (hiz), 15 DRVEN (in), 16 VCC (power) hidden to VCC
2 alternate drawings of the same symbol

## 8T28
designator U?
footprint DIP-16
pins: 1 RxEN (in), 2 RxOUT1 (hiz), 3 BUS1 (hiz), 4 DRVin1 (hiz), 5 RxOUT2 (hiz), 6 BUS2 (hiz), 7 DRVin2 (hiz), 8 GND (power) hidden to GND, 9 DRVin3 (hiz), 10 BUS3 (hiz), 11 RxOUT3 (hiz), 12 DRVin4 (hiz), 13 BUS4 (hiz), 14 RxOUT4 (hiz), 15 DRVEN (in), 16 VCC (power) hidden to VCC
2 alternate drawings of the same symbol

## 2681
designator U?
footprint DIP-40
pins: 1 RS1 (in), 2 IP3 (in), 3 RS2 (in), 4 IP1 (in), 5 RS3 (in), 6 RS4 (in), 7 IP0 (in), 8 W (in), 9 R (in), 10 RxDB (in), 11 TxDB (out), 12 OP1 (out), 13 OP3 (oc), 14 OP5 (oc), 15 OP7 (oc), 16 D1 (hiz), 17 D3 (hiz), 18 D5 (hiz), 19 D7 (hiz), 20 GND (power) hidden to GND, 21 IRQ (oc), 22 D6 (hiz), 23 D4 (hiz), 24 D2 (hiz), 25 D0 (hiz), 26 OP6 (oc), 27 OP4 (oc), 28 OP2 (out), 29 OP0 (out), 30 TxDA (out), 31 RxDA (in), 32 X1/CLK (in), 33 X2 (in), 34 RESET (in), 35 CS (in), 36 IP2 (in), 37 IP6 (in), 38 IP5 (in), 39 IP4 (in), 40 VCC (power) hidden to VCC
2 alternate drawings of the same symbol

## 2682
designator U?
footprint DIP-28
pins: 1 RS1 (in), 2 RS2 (in), 3 RS3 (in), 4 RS4 (in), 5 W (in), 6 R (in), 7 RxDB (in), 8 TxDB (out), 9 OP1 (out), 10 D1 (hiz), 11 D3 (hiz), 12 D5 (hiz), 13 D7 (hiz), 14 GND (power) hidden to GND, 15 IRQ (oc), 16 D6 (hiz), 17 D4 (hiz), 18 D2 (hiz), 19 D0 (hiz), 20 OP0 (out), 21 TxDA (out), 22 RxDA (in), 23 X1/CLK (in), 24 X2 (in), 25 RESET (in), 26 CS (in), 27 IP2 (in), 28 VCC (power) hidden to VCC
2 alternate drawings of the same symbol

## 6800
designator U?
footprint DIP-40
pins: 1 GND (power) hidden to GND, 2 HALT (in), 3 CLK01 (in), 4 IRQ (in), 5 VMA (out), 6 NMI (in), 7 BA (out), 8 VCC (power) hidden to VCC, 9 A0 (hiz), 10 A1 (hiz), 11 A2 (hiz), 12 A3 (hiz), 13 A4 (hiz), 14 A5 (hiz), 15 A6 (hiz), 16 A7 (hiz), 17 A8 (hiz), 18 A9 (hiz), 19 A10 (hiz), 20 A11 (hiz), 21 GND (power) hidden to GND, 22 A12 (hiz), 23 A13 (hiz), 24 A14 (hiz), 25 A15 (hiz), 26 D7 (hiz), 27 D6 (hiz), 28 D5 (hiz), 29 D4 (hiz), 30 D3 (hiz), 31 D2 (hiz), 32 D1 (hiz), 33 D0 (hiz), 34 R/~{W} (out), 36 DBE (in), 37 CLK02 (in), 39 TSC (out), 40 RESET (in)
2 alternate drawings of the same symbol

## 6801
designator U?
footprint DIP-40
pins: 1 GND (power) hidden to GND, 2 XTAL1 (in), 3 EXTAL2 (in), 4 NMI (in), 5 IRQ1 (in), 6 RESET (in), 7 VCC (power) hidden to VCC, 8 P20 (hiz), 9 P21 (hiz), 10 P22 (hiz), 11 P23 (hiz), 12 P24 (hiz), 13 P10 (hiz), 14 P11 (hiz), 15 P12 (hiz), 16 P13 (hiz), 17 P14 (hiz), 18 P15 (hiz), 19 P16 (hiz), 20 P17 (hiz), 21 VccSTB (in), 22 P47 (io), 23 P46 (io), 24 P45 (io), 25 P44 (io), 26 P43 (io), 27 P42 (io), 28 P41 (io), 29 P40 (io), 30 P37 (hiz), 31 P36 (hiz), 32 P35 (hiz), 33 P34 (hiz), 34 P33 (hiz), 35 P32 (hiz), 36 P31 (hiz), 37 P30 (hiz), 38 SC2 (out), 39 SC1 (io), 40 E (out)
2 alternate drawings of the same symbol

## 6802
designator U?
footprint DIP-40
pins: 1 GND (power) hidden to GND, 2 HALT (in), 3 MR (in), 4 IRQ (in), 5 VMA (out), 6 NMI (in), 7 BA (out), 8 VCC (power) hidden to VCC, 9 A0 (io), 10 A1 (io), 11 A2 (io), 12 A3 (io), 13 A4 (io), 14 A5 (io), 15 A6 (io), 16 A7 (io), 17 A8 (io), 18 A9 (io), 19 A10 (io), 20 A11 (io), 21 GND (power) hidden to GND, 22 A12 (io), 23 A13 (io), 24 A14 (io), 25 A15 (io), 26 D7 (hiz), 27 D6 (hiz), 28 D5 (hiz), 29 D4 (hiz), 30 D3 (hiz), 31 D2 (hiz), 32 D1 (hiz), 33 D0 (hiz), 34 R/~{W} (out), 35 VccSTB (in), 36 RE (in), 37 E (out), 38 XTAL (in), 39 EXTAL (in), 40 RESET (in)
2 alternate drawings of the same symbol

## 6805E2
designator U?
footprint DIP-40
pins: 1 RESET (in), 2 IRQ (in), 3 L-INST (out), 4 DS (out), 5 R/~{W} (out), 6 AS (out), 7 PA7 (hiz), 8 PA6 (hiz), 9 PA5 (hiz), 10 PA4 (hiz), 11 PA3 (hiz), 12 PA2 (hiz), 13 PA1 (hiz), 14 PA0 (hiz), 15 A12 (out), 16 A11 (out), 17 A10 (out), 18 A9 (out), 19 A8 (out), 20 GND (power) hidden to GND, 21 B7 (hiz), 22 B6 (hiz), 23 B5 (hiz), 24 B4 (hiz), 25 B3 (hiz), 26 B2 (hiz), 27 B1 (hiz), 28 B0 (hiz), 29 PB7 (hiz), 30 PB6 (hiz), 31 PB5 (hiz), 32 PB4 (hiz), 33 PB3 (hiz), 34 PB2 (hiz), 35 PB1 (hiz), 36 PB0 (hiz), 37 TIMER (in), 38 OSC-2 (out), 39 OSC-1 (in), 40 VCC (power) hidden to VCC
2 alternate drawings of the same symbol

## 6805P2
designator U?
footprint DIP-28
pins: 1 GND (power) hidden to GND, 2 INT (in), 3 VCC (power) hidden to VCC, 4 EXTAL (in), 5 XTAL (in), 6 NUM (in), 7 TIMER (in), 8 PC0 (io), 9 PC1 (io), 10 PC2 (io), 11 PC3 (io), 12 PB0 (io), 13 PB1 (io), 14 PB2 (io), 15 PB3 (io), 16 PB4 (io), 17 PB5 (io), 18 PB6 (io), 19 PB7 (io), 20 PA0 (io), 21 PA1 (io), 22 PA2 (io), 23 PA3 (io), 24 PA4 (io), 25 PA5 (io), 26 PA6 (io), 27 PA7 (io), 28 RESET (in)
2 alternate drawings of the same symbol

## 6805P4
designator U?
footprint DIP-28
pins: 1 GND (power) hidden to GND, 2 INT (in), 3 VCC (power) hidden to VCC, 4 EXTAL (in), 5 XTAL (in), 6 Vsb (in), 7 TIMER (in), 8 PC0NUM (io), 9 PC1 (io), 10 PC2 (io), 11 PC3 (io), 12 PB0 (io), 13 PB1 (io), 14 PB2 (io), 15 PB3 (io), 16 PB4 (io), 17 PB5 (io), 18 PB6 (io), 19 PB7 (io), 20 PA0 (io), 21 PA1 (io), 22 PA2 (io), 23 PA3 (io), 24 PA4 (io), 25 PA5 (io), 26 PA6 (io), 27 PA7 (io), 28 RESET (in)
2 alternate drawings of the same symbol

## 6805R2
designator U?
footprint DIP-40
pins: 1 GND (power) hidden to GND, 2 RESET (in), 3 INT (in), 4 VCC (power) hidden to VCC, 5 EXTAL (in), 6 XTAL (in), 7 NUM (in), 8 TIMER (in), 9 PC0 (io), 10 PC1 (io), 11 PC2 (io), 12 PC3 (io), 13 PC4 (io), 14 PC5 (io), 15 PC6 (io), 16 PC7 (io), 17 PD7 (in), 18 PD6/~{I2} (in), 19 PD5Vrh (in), 20 PD4Vrl (in), 21 PD/AN3 (in), 22 PD/AN2 (in), 23 PD/AN1 (in), 24 PD/AN0 (in), 25 PB0 (io), 26 PB1 (io), 27 PB2 (io), 28 PB3 (io), 29 PB4 (io), 30 PB5 (io), 31 PB6 (io), 32 PB7 (io), 33 PA0 (io), 34 PA1 (io), 35 PA2 (io), 36 PA3 (io), 37 PA4 (io), 38 PA5 (io), 39 PA6 (io), 40 PA7 (io)
2 alternate drawings of the same symbol

## 6805R3
designator U?
footprint DIP-40
pins: 1 GND (power) hidden to GND, 2 RESET (in), 3 INT (in), 4 VCC (power) hidden to VCC, 5 EXTAL (in), 6 XTAL (in), 8 TIMER (in), 9 PC0 (io), 10 PC1 (io), 11 PC2 (io), 12 PC3 (io), 13 PC4 (io), 14 PC5 (io), 15 PC6 (io), 16 PC7 (io), 17 PD7 (in), 18 PD6/~{I2} (in), 19 PD5Vrh (in), 20 PD4Vrl (in), 21 PD/AN3 (in), 22 PD/AN2 (in), 23 PD/AN1 (in), 24 PD/AN0 (in), 25 PB0 (io), 26 PB1 (io), 27 PB2 (io), 28 PB3 (io), 29 PB4 (io), 30 PB5 (io), 31 PB6 (io), 32 PB7 (io), 33 PA0 (io), 34 PA1 (io), 35 PA2 (io), 36 PA3 (io), 37 PA4 (io), 38 PA5 (io), 39 PA6 (io), 40 PA7 (io)
2 alternate drawings of the same symbol

## 6805T2
designator U?
footprint DIP-28
pins: 1 GND (power) hidden to GND, 2 INT (in), 3 VCC (power) hidden to VCC, 4 EXTAL (in), 5 XTAL (in), 6 NUM (in), 7 0COMP (hiz), 8 PC0TIM (io), 9 PC1 (io), 10 PC2 (io), 11 Fin (in), 12 PB0 (io), 13 PB1 (io), 14 PB2 (io), 15 PB3 (io), 16 PB4 (io), 17 PB5 (io), 18 PB6 (io), 19 PB7 (io), 20 PA0 (io), 21 PA1 (io), 22 PA2 (io), 23 PA3 (io), 24 PA4 (io), 25 PA5 (io), 26 PA6 (io), 27 PA7 (io), 28 RESET (in)
2 alternate drawings of the same symbol

## 6805U2
designator U?
footprint DIP-40
pins: 1 GND (power) hidden to GND, 2 RESET (in), 3 INT (in), 4 VCC (power) hidden to VCC, 5 EXTAL (in), 6 XTAL (in), 7 NUM (in), 8 TIMER (in), 9 PC0 (io), 10 PC1 (io), 11 PC2 (io), 12 PC3 (io), 13 PC4 (io), 14 PC5 (io), 15 PC6 (io), 16 PC7 (io), 17 PD7 (in), 18 PD6/~{I2} (in), 19 PD5 (in), 20 PD4 (in), 21 PD3 (in), 22 PD2 (in), 23 PD1 (in), 24 PD0 (in), 25 PB0 (io), 26 PB1 (io), 27 PB2 (io), 28 PB3 (io), 29 PB4 (io), 30 PB5 (io), 31 PB6 (io), 32 PB7 (io), 33 PA0 (io), 34 PA1 (io), 35 PA2 (io), 36 PA3 (io), 37 PA4 (io), 38 PA5 (io), 39 PA6 (io), 40 PA7 (io)
2 alternate drawings of the same symbol

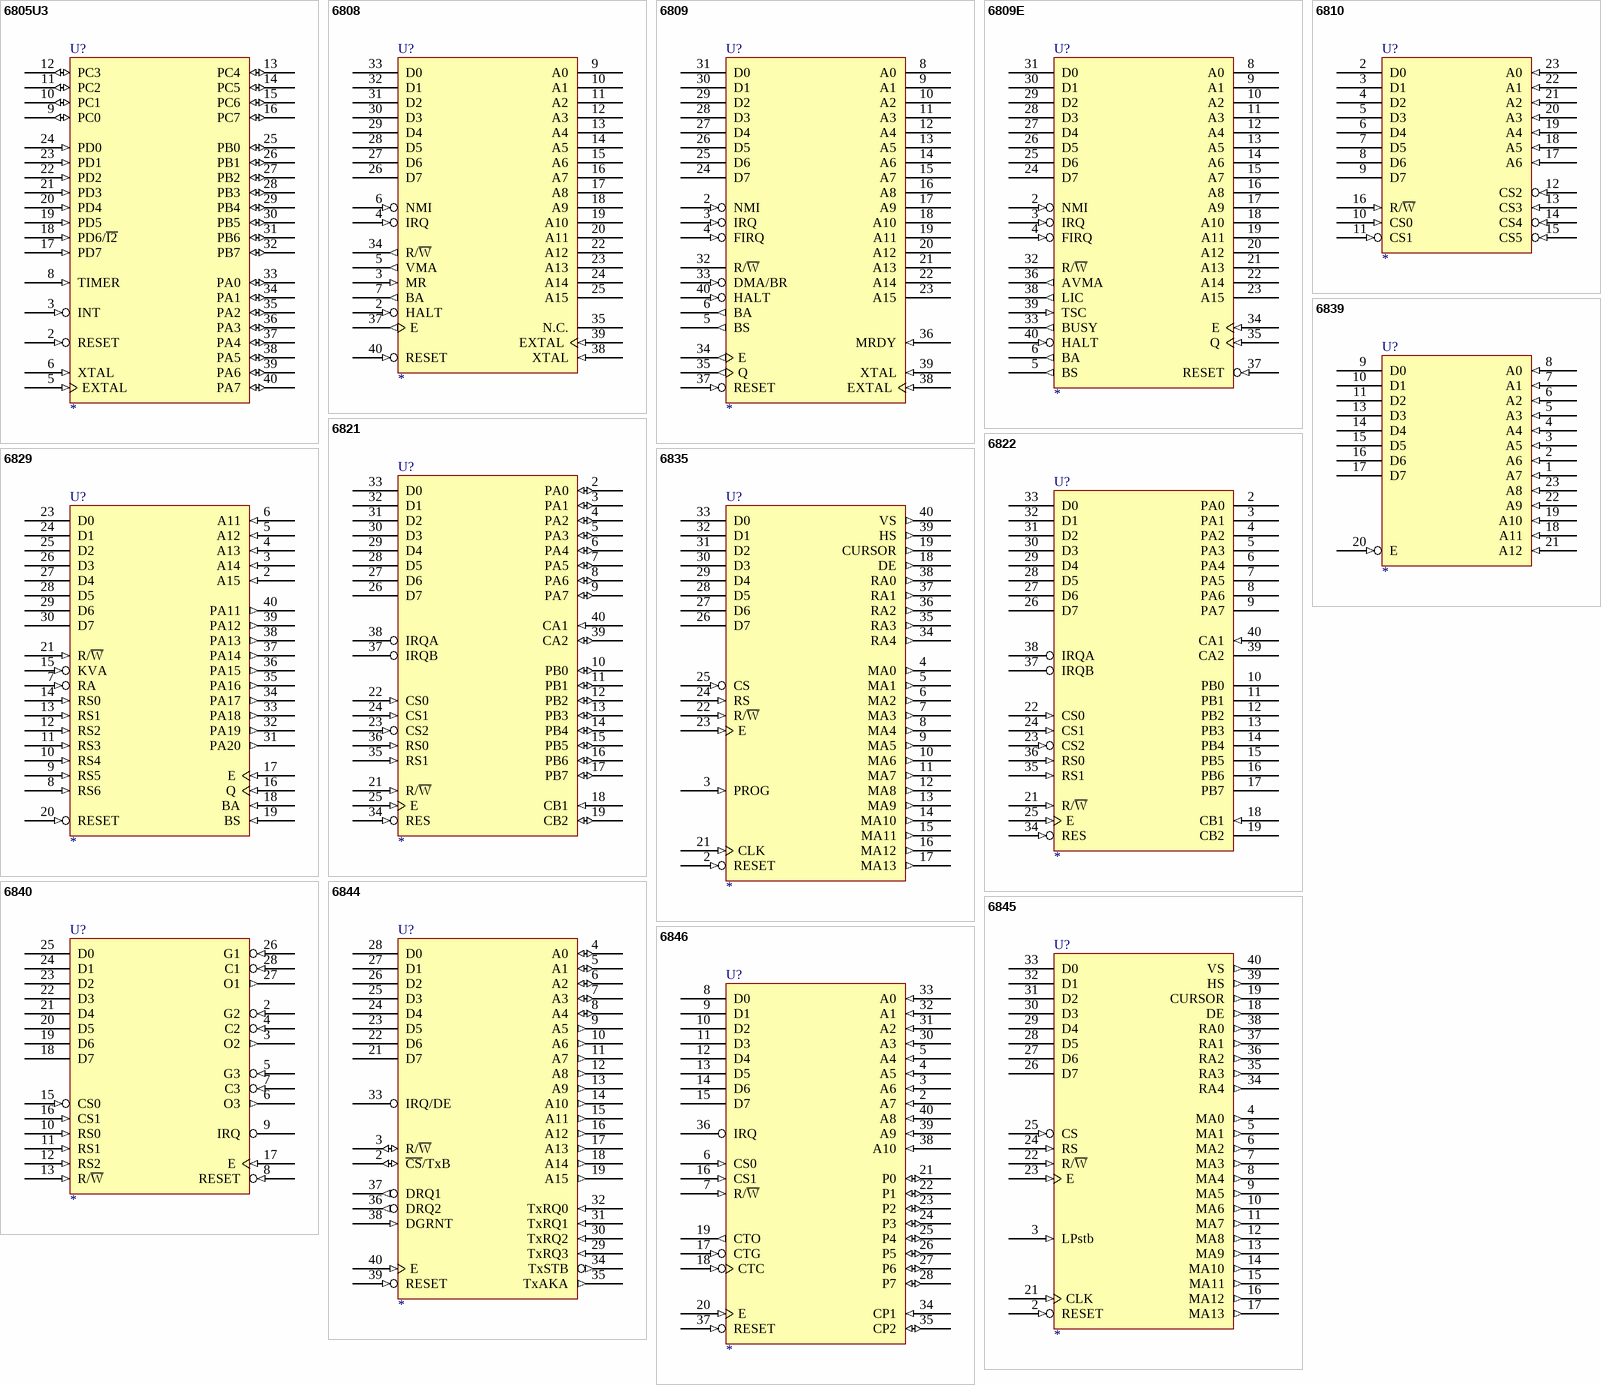
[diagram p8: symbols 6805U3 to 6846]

## 6805U3
designator U?
footprint DIP-40
pins: 1 GND (power) hidden to GND, 2 RESET (in), 3 INT (in), 4 VCC (power) hidden to VCC, 5 EXTAL (in), 6 XTAL (in), 8 TIMER (in), 9 PC0 (io), 10 PC1 (io), 11 PC2 (io), 12 PC3 (io), 13 PC4 (io), 14 PC5 (io), 15 PC6 (io), 16 PC7 (io), 17 PD7 (in), 18 PD6/~{I2} (in), 19 PD5 (in), 20 PD4 (in), 21 PD3 (in), 22 PD2 (in), 23 PD1 (in), 24 PD0 (in), 25 PB0 (io), 26 PB1 (io), 27 PB2 (io), 28 PB3 (io), 29 PB4 (io), 30 PB5 (io), 31 PB6 (io), 32 PB7 (io), 33 PA0 (io), 34 PA1 (io), 35 PA2 (io), 36 PA3 (io), 37 PA4 (io), 38 PA5 (io), 39 PA6 (io), 40 PA7 (io)
2 alternate drawings of the same symbol

## 6808
designator U?
footprint DIP-40
pins: 1 GND (power) hidden to GND, 2 HALT (in), 3 MR (in), 4 IRQ (in), 5 VMA (out), 6 NMI (in), 7 BA (out), 8 VCC (power) hidden to VCC, 9 A0 (hiz), 10 A1 (hiz), 11 A2 (hiz), 12 A3 (hiz), 13 A4 (hiz), 14 A5 (hiz), 15 A6 (hiz), 16 A7 (hiz), 17 A8 (hiz), 18 A9 (hiz), 19 A10 (hiz), 20 A11 (hiz), 21 GND (power) hidden to GND, 22 A12 (hiz), 23 A13 (hiz), 24 A14 (hiz), 25 A15 (hiz), 26 D7 (hiz), 27 D6 (hiz), 28 D5 (hiz), 29 D4 (hiz), 30 D3 (hiz), 31 D2 (hiz), 32 D1 (hiz), 33 D0 (hiz), 34 R/~{W} (out), 35 N.C., 36 GND (power) hidden to GND, 37 E (out), 38 XTAL (in), 39 EXTAL (in), 40 RESET (in)
2 alternate drawings of the same symbol

## 6809
designator U?
footprint DIP-40
pins: 1 GND (power) hidden to GND, 2 NMI (in), 3 IRQ (in), 4 FIRQ (in), 5 BS (out), 6 BA (out), 7 VCC (power) hidden to VCC, 8 A0 (hiz), 9 A1 (hiz), 10 A2 (hiz), 11 A3 (hiz), 12 A4 (hiz), 13 A5 (hiz), 14 A6 (hiz), 15 A7 (hiz), 16 A8 (hiz), 17 A9 (hiz), 18 A10 (hiz), 19 A11 (hiz), 20 A12 (hiz), 21 A13 (hiz), 22 A14 (hiz), 23 A15 (hiz), 24 D7 (hiz), 25 D6 (hiz), 26 D5 (hiz), 27 D4 (hiz), 28 D3 (hiz), 29 D2 (hiz), 30 D1 (hiz), 31 D0 (hiz), 32 R/~{W} (hiz), 33 DMA/BR (in), 34 E (out), 35 Q (out), 36 MRDY (in), 37 RESET (in), 38 EXTAL (in), 39 XTAL (in), 40 HALT (in)
2 alternate drawings of the same symbol

## 6809E
designator U?
footprint DIP-40
pins: 1 GND (power) hidden to GND, 2 NMI (in), 3 IRQ (in), 4 FIRQ (in), 5 BS (out), 6 BA (out), 7 VCC (power) hidden to VCC, 8 A0 (hiz), 9 A1 (hiz), 10 A2 (hiz), 11 A3 (hiz), 12 A4 (hiz), 13 A5 (hiz), 14 A6 (hiz), 15 A7 (hiz), 16 A8 (hiz), 17 A9 (hiz), 18 A10 (hiz), 19 A11 (hiz), 20 A12 (hiz), 21 A13 (hiz), 22 A14 (hiz), 23 A15 (hiz), 24 D7 (hiz), 25 D6 (hiz), 26 D5 (hiz), 27 D4 (hiz), 28 D3 (hiz), 29 D2 (hiz), 30 D1 (hiz), 31 D0 (hiz), 32 R/~{W} (hiz), 33 BUSY (out), 34 E (in), 35 Q (in), 36 AVMA (out), 37 RESET (in), 38 LIC (out), 39 TSC (in), 40 HALT (in)
2 alternate drawings of the same symbol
